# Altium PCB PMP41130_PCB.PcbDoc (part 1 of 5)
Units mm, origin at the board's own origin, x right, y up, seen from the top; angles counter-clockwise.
Board outline 74.13 x 200.91 mm, 6 copper layers (Top Layer, Layer 1, Inside Layer 1, Inside Layer 2, Layer 2, Bottom Layer), stack 2.208 mm thick; 356 components, 162 nets, 889 pads, 1511 vias.
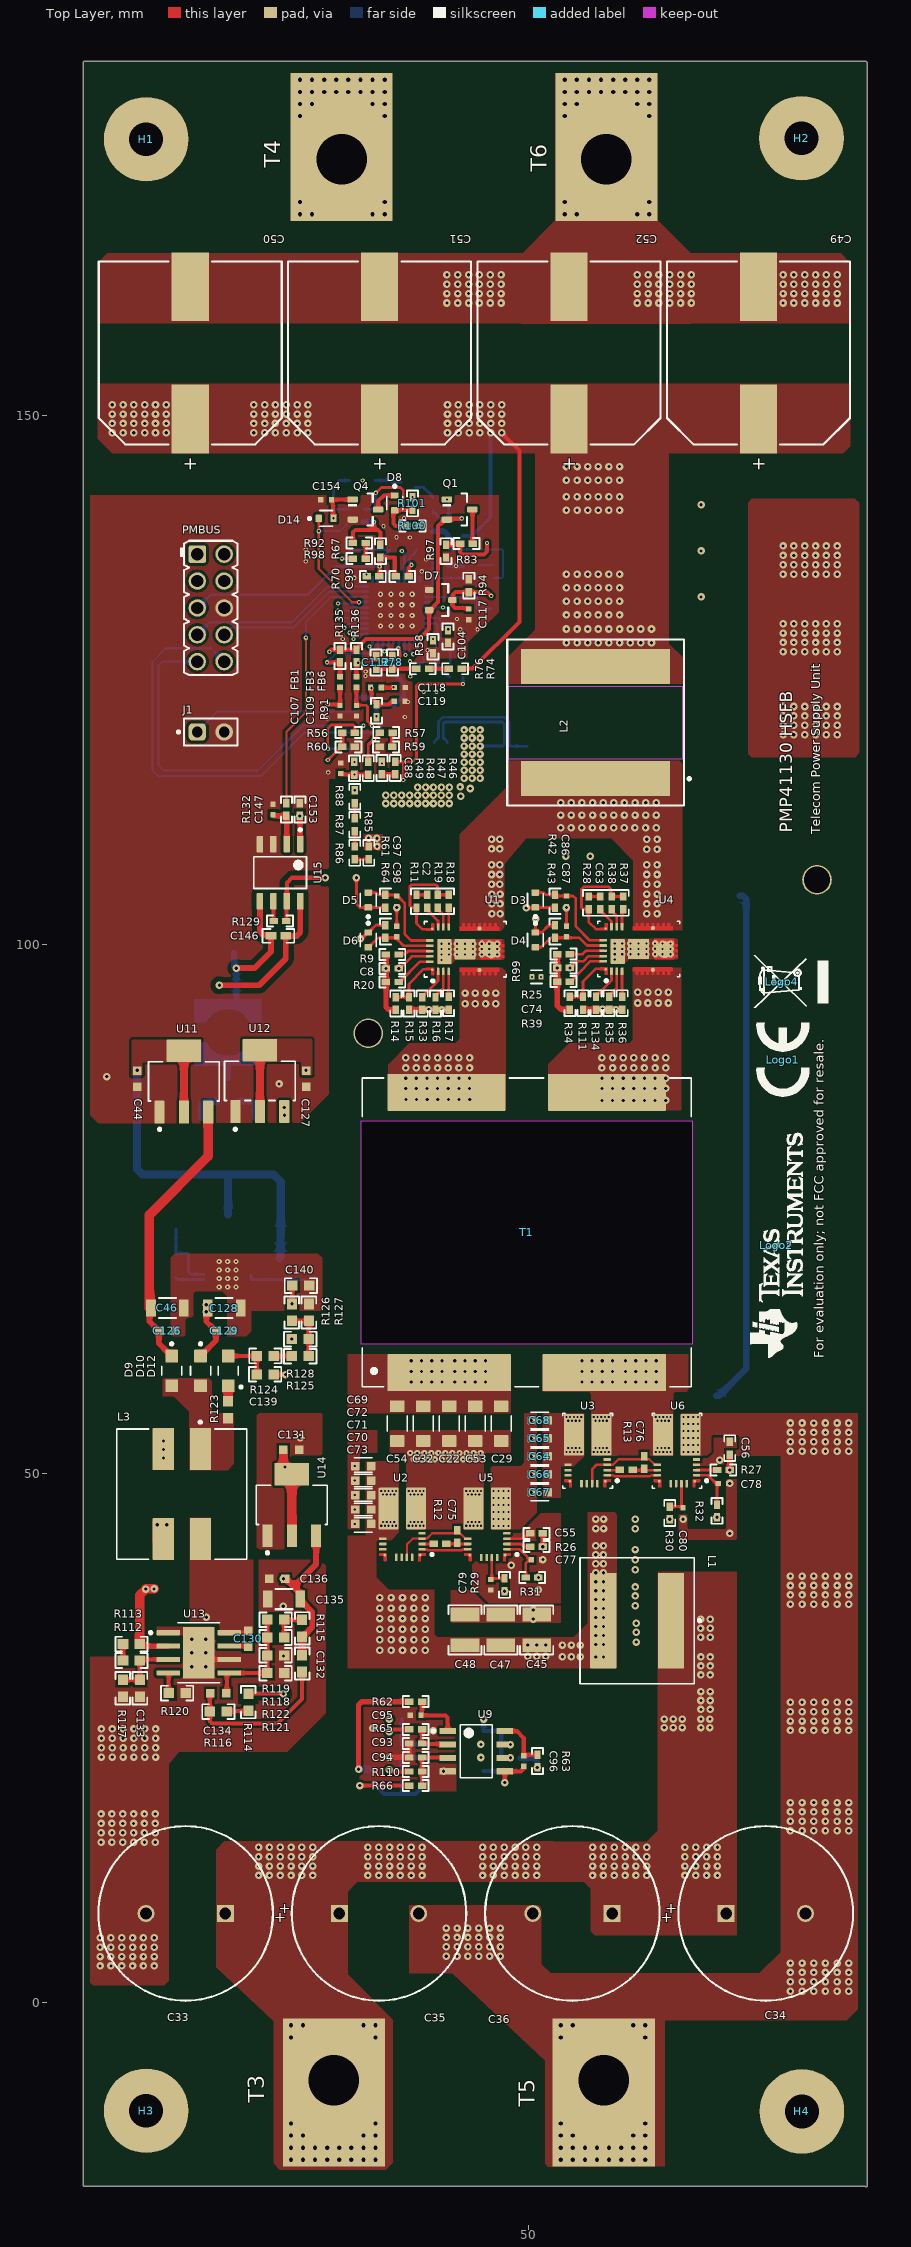
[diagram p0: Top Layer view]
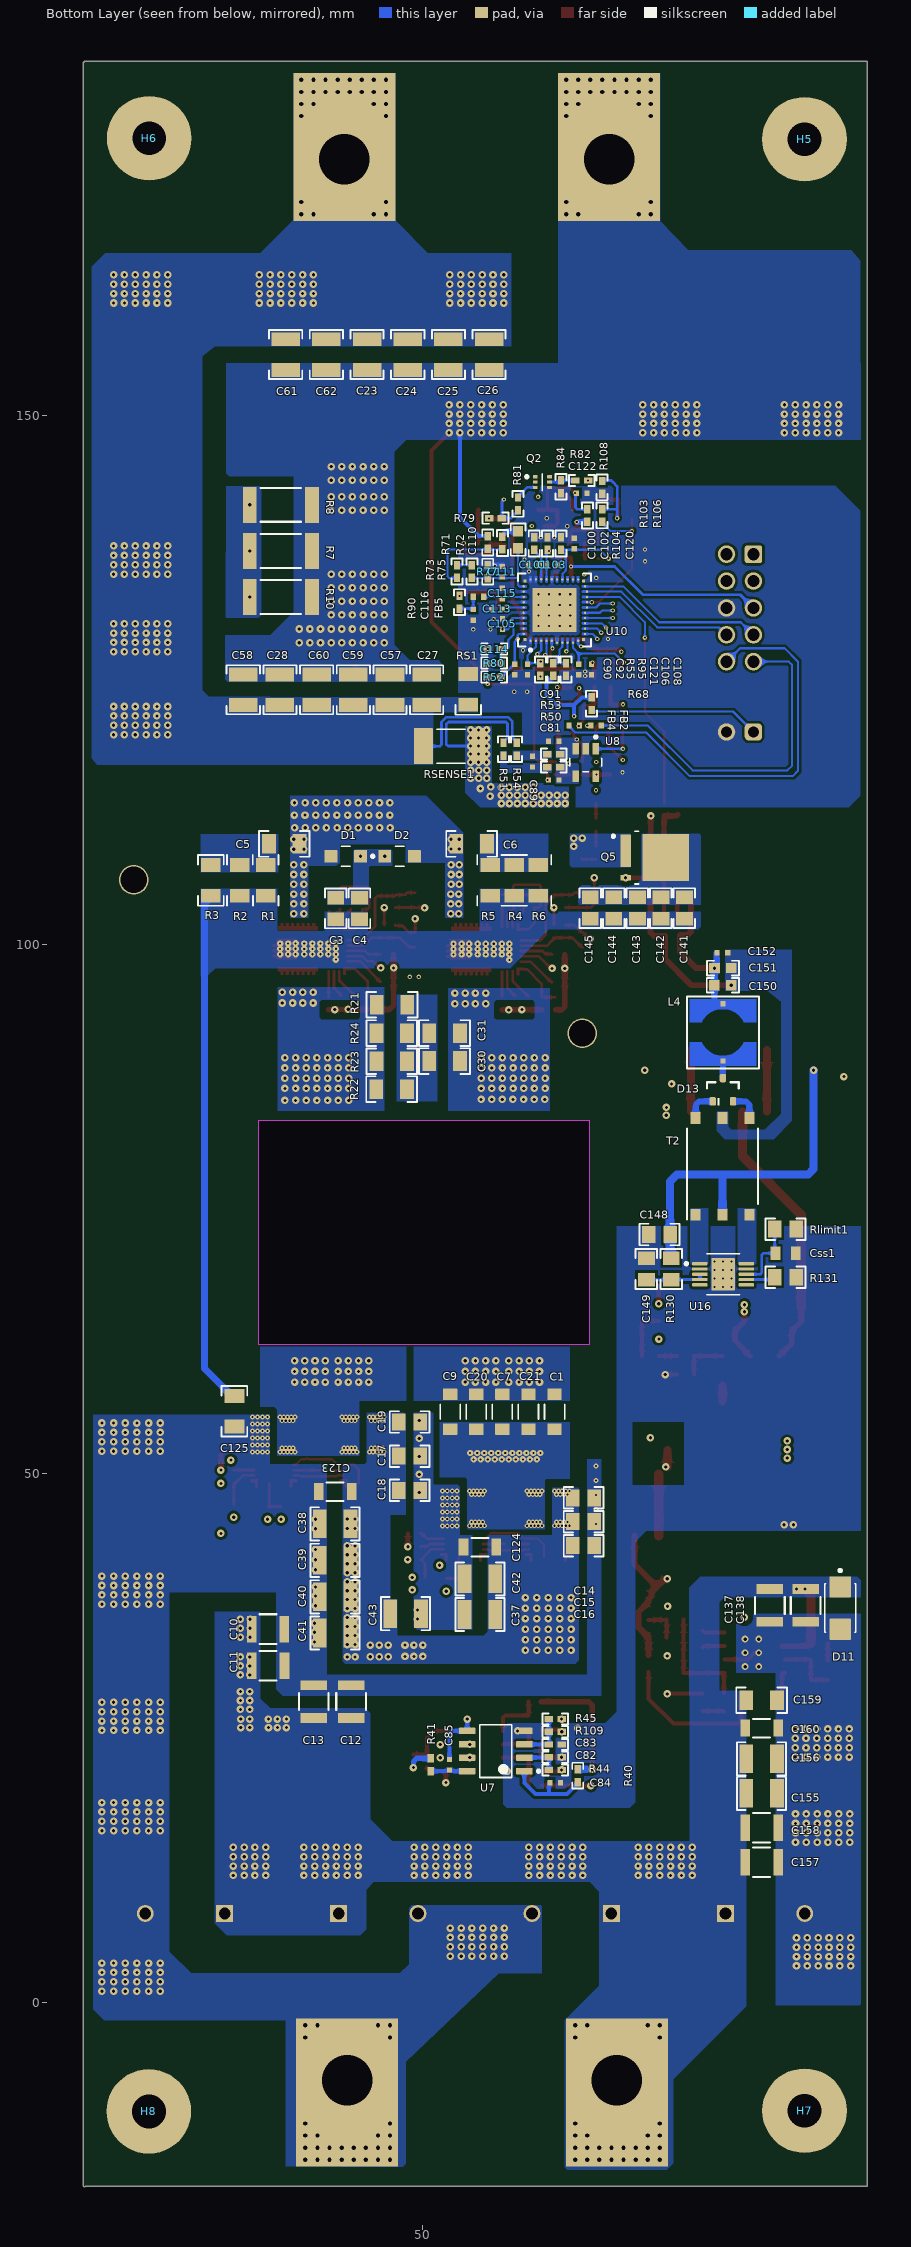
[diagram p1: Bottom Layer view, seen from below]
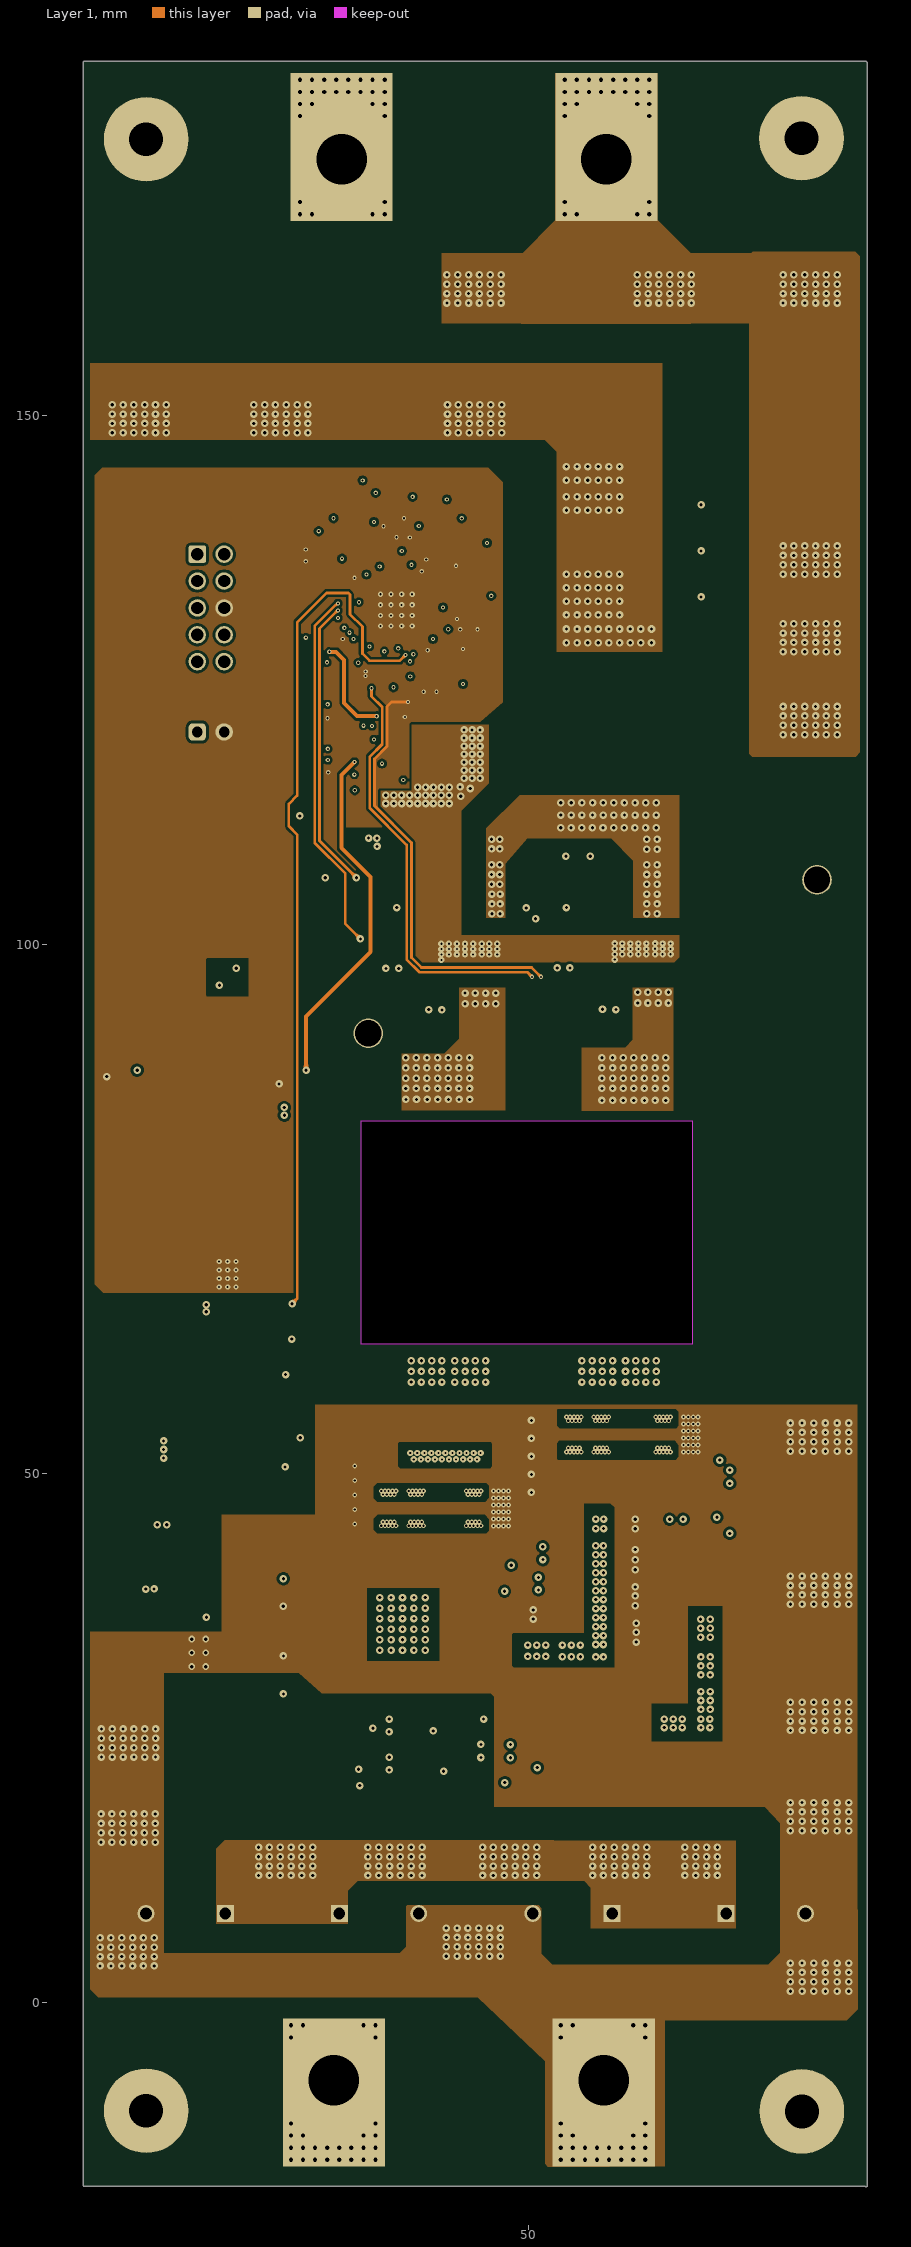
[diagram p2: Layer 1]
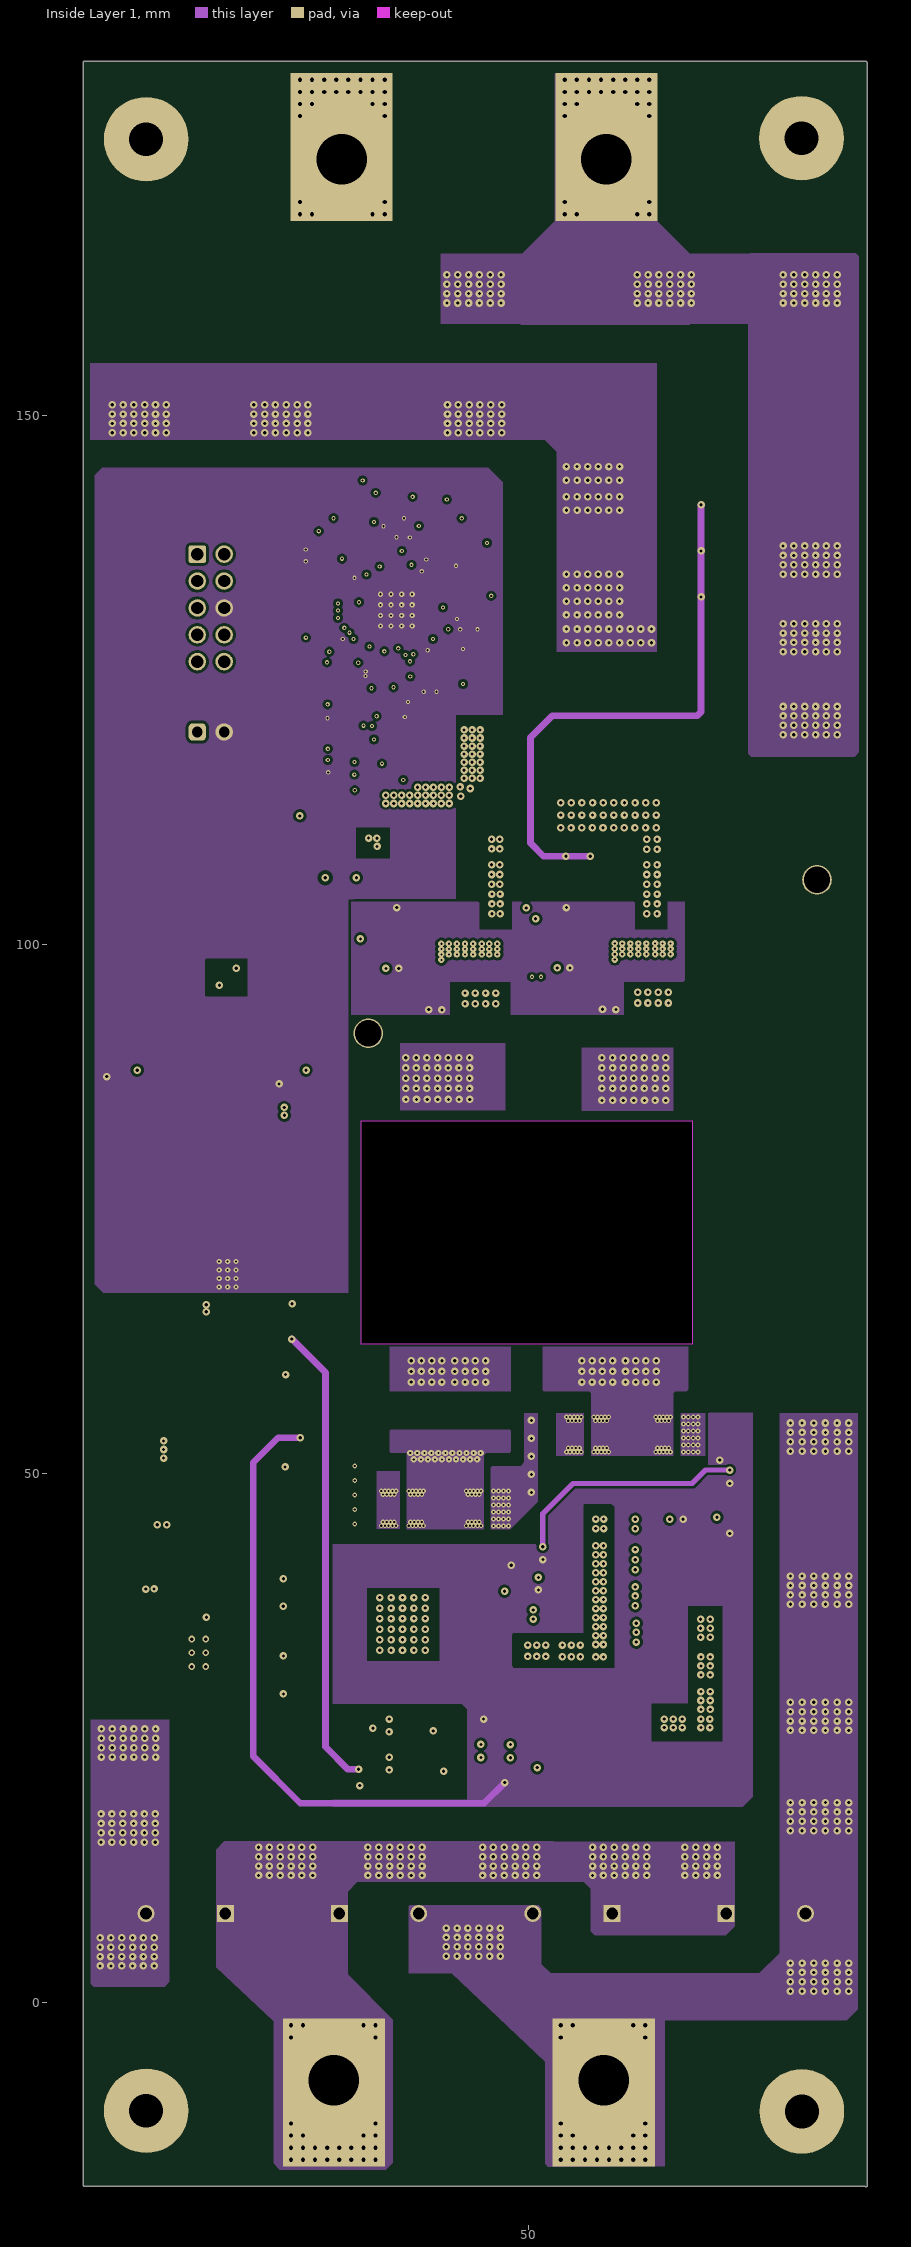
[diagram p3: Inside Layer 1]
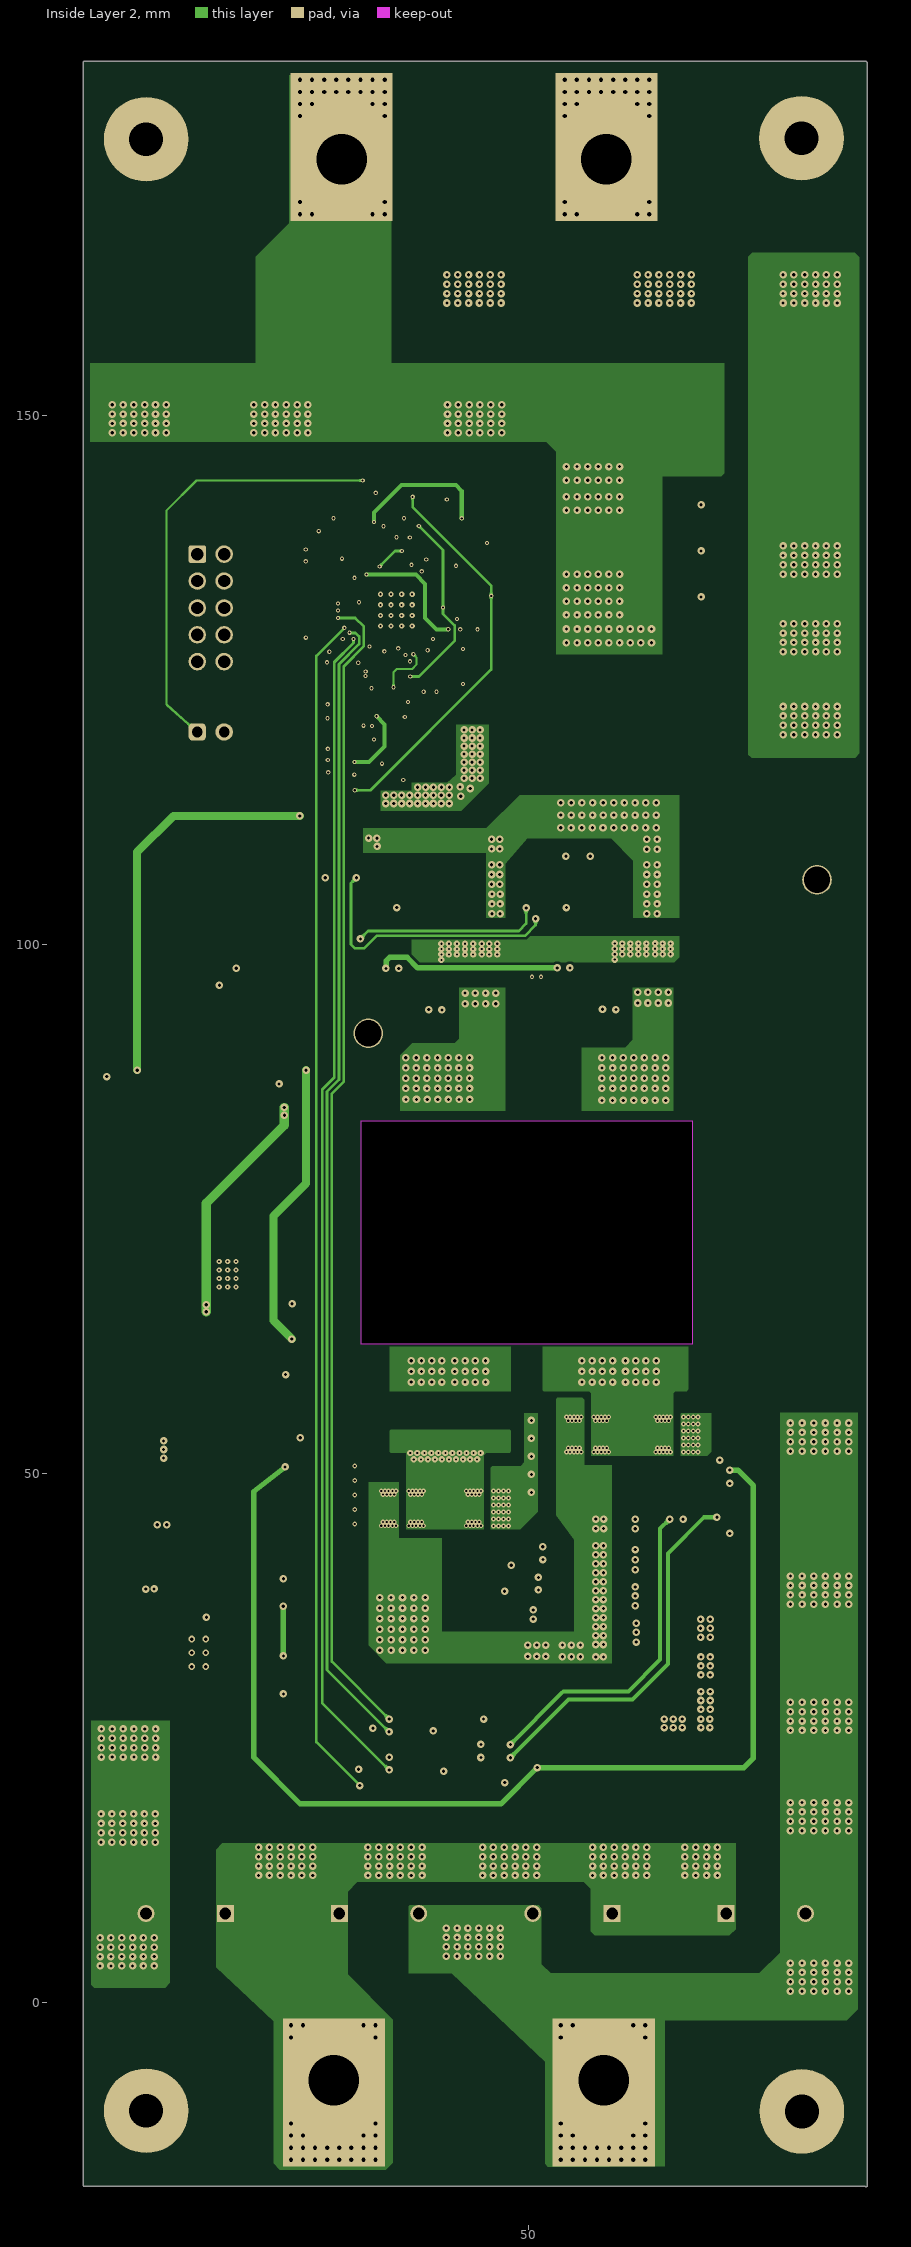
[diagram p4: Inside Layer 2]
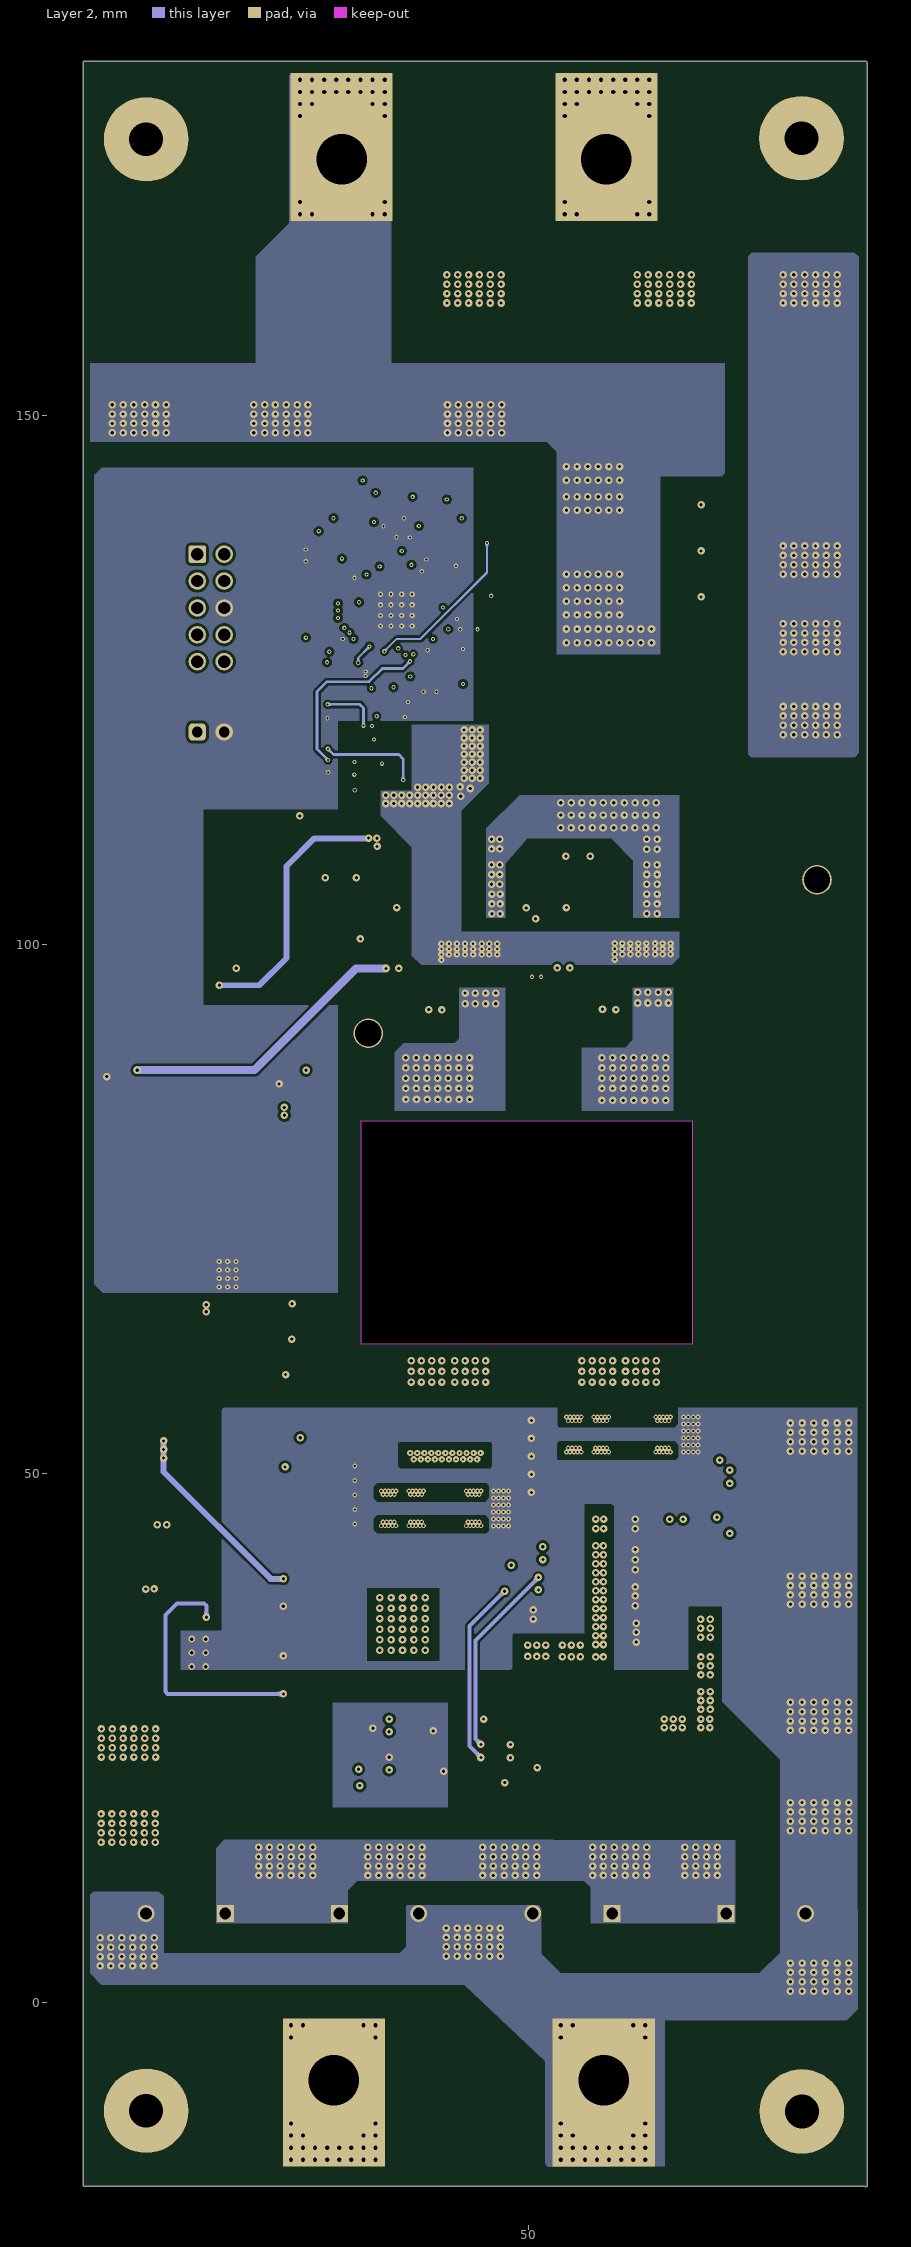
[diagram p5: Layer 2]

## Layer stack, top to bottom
Top Solder: solder mask 0.0102, Solder Resist, Dk 3.5
Top Layer: signal copper 0.07
Dielectric 3: prepreg 0.0711, PP-006, Dk 4.1
Layer 1: signal copper 0.07
Dielectric 1: prepreg 0.0711, PP-006, Dk 4.1
Inside Layer 1: signal copper 0.07
Dielectric1: core 1.5037, FR-4 High Tg, Dk 4.8
Inside Layer 2: signal copper 0.07
Dielectric 2: prepreg 0.0711, PP-006, Dk 4.1
Layer 2: signal copper 0.07
Dielectric 4: prepreg 0.0711, PP-006, Dk 4.1
Bottom Layer: signal copper 0.07
Bottom Solder: solder mask 0.0102, Solder Resist, Dk 3.5

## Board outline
7.918,-17.3 7.918,183.3 7.919,183.313 cw(c8.046,183.325) 8.046,183.453 81.855,183.453 cw(c81.855,183.325) 81.967,183.386 cw(c81.919,183.268) 82.046,183.268 82.046,-17.331 cw(c81.919,-17.331) 81.839,-17.43 8.077,-17.43 8.048,-17.427 cw(c8.046,-17.3)

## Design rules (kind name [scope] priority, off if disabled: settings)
AcuteAngle [All] p1: minimum=4.50000000000000E+0001 checktracksonly=FALSE
AssemblyTestPointUsage [All] p1: valid=2
BoardOutlineClearance BoardOutlineClearance_MountingHoles [OnCopper and InComponentClass('Mounting Holes')] p1: gap=1 ignorepadtopadclearanceinfootprint=FALSE
BoardOutlineClearance BoardOutlineClearance_Poly [OnCopper and IsPoly] p2: gap=0.635 ignorepadtopadclearanceinfootprint=FALSE
BoardOutlineClearance [OnCopper and Not InComponentClass('Logo') and not InComponentClass('FiducialMark') and not InRegion(1000,500,4000,800) and not InPoly] p3: gap=1.016 ignorepadtopadclearanceinfootprint=FALSE
Clearance Clearance_Keepouts [((IsTrack Or IsArc) And Not InPoly) And IsFree and IsKeepOut vs ((IsTrack Or IsArc) And Not InPoly) And IsFree and IsKeepOut] p1: gap=3 ignorepadtopadclearanceinfootprint=TRUE
Clearance Clearance_FiducialMark [IsKeepOut and InComponentClass('FiducialMark') vs IsPad and InComponentClass('FiducialMark')] p2: gap=3 ignorepadtopadclearanceinfootprint=FALSE
Clearance RPI_GaN [InComponent('U2') or InComponent('U3') or  InComponent('U5') or InComponent('U6') vs InNet('HB1_MID') or InNet('HB2_MID') or InNet('HS_Drain') or InNet('SW1') or InNet('SW2')] p3: gap=0.23 ignorepadtopadclearanceinfootprint=TRUE
Clearance PRI_GaN1 [InNet('SW1','SW2') vs InNet('HB1_MID','HB2_MID')] p4: gap=0.23 ignorepadtopadclearanceinfootprint=TRUE
Clearance MV_TOP [InNetClass('MIDVOLTAGE') vs OnLayer('Top Layer')] p5: gap=0.5 ignorepadtopadclearanceinfootprint=TRUE
Clearance MV_BOTTOM [InNetClass('MIDVOLTAGE') vs OnLayer('Bottom Layer')] p6: gap=0.5 ignorepadtopadclearanceinfootprint=TRUE
Clearance MV_MID [(OnMultiLayer Or OnMid) And InNetClass('MIDVOLTAGE') vs OnMid And Not InNetClass('MIDVOLTAGE')] p7: gap=0.35 ignorepadtopadclearanceinfootprint=TRUE
Clearance Clearance_Poly [InPolygon] p8: gap=0.254 ignorepadtopadclearanceinfootprint=TRUE
Clearance [All] p9: gap=0.2 ignorepadtopadclearanceinfootprint=TRUE
ComponentClearance ComponentClearance_MountingHoles_FiducialMarks [InComponentClass('Mounting Holes') vs InComponentClass('FiducialMark')] p1: gap=1.27 collisioncheckmode=3 verticalgap=0.254 showdistances=FALSE
ComponentClearance ComponentClearance_Shunt [InComponentClass('Header') vs InComponentClass('Shunt')] p2: gap=0 collisioncheckmode=3 verticalgap=0 showdistances=FALSE
ComponentClearance ComponentClearance_Logo [InComponentClass('Logo')] p3: gap=0.762 collisioncheckmode=3 verticalgap=0.254 showdistances=FALSE
ComponentClearance ComponentClearance_ScrewToNut [(HasFootprint('NY PMS 440 0025 PH')) vs (HasFootprint('Keystone_1902C'))] p4: gap=0.127 collisioncheckmode=3 verticalgap=0.254 showdistances=FALSE
ComponentClearance ComponentClearance_MountingHoles [InComponentClass('Mounting Holes')] p5: gap=2.54 collisioncheckmode=3 verticalgap=2540 showdistances=FALSE
ComponentClearance ComponentClearance_SmallPassives [HasFootprint('0201*') or HasFootprint('0402*') or HasFootprint('0508') or HasFootprint('0603*') or HasFootprint('0612') or HasFootprint('0805*') or HasFootprint('0815*') or HasFootprint('0830*') or HasFootprint('1206*') or HasFootprint('1210*') or HasFootprint('1808*') or HasFootprint('1812*') or HasFootprint('1825*') or HasFootprint('2010*') or HasFootprint('2220*') or HasFootprint('2225*') or HasFootprint('2512*') or HasFootprint('2728*') or HasFootprint('3518*') vs HasFootprint('0201*') or HasFootprint('0402*') or HasFootprint('0508') or HasFootprint('0603*') or HasFootprint('0612') or HasFootprint('0805*') or HasFootprint('0815*') or HasFootprint('0830*') or HasFootprint('1206*') or HasFootprint('1210*') or HasFootprint('1808*') or HasFootprint('1812*') or HasFootprint('1825*') or HasFootprint('2010*') or HasFootprint('2220*') or HasFootprint('2225*') or HasFootprint('2512*') or HasFootprint('2728*') or HasFootprint('3518*')] p6: gap=0.38 collisioncheckmode=3 verticalgap=0.254 showdistances=FALSE
ComponentClearance ComponentClearance_THtoSMT [IsThruComponent vs IsSMTComponent] p7: gap=0.762 collisioncheckmode=3 verticalgap=0.762 showdistances=FALSE
ComponentClearance ComponentClearance_THtoTH [IsThruComponent vs IsThruComponent] p8: gap=0.508 collisioncheckmode=3 verticalgap=0.762 showdistances=FALSE
ComponentClearance [All] p9: gap=0.508 collisioncheckmode=3 verticalgap=0.254 showdistances=FALSE
DiffPairsRouting [All] p1: maxlimit=2.54 minlimit=0.254 mostfreqgap=0.254 toplayer_minwidth=0.381 toplayer_maxwidth=0.381 toplayer_prefwidth=0.381 midlayer1_minwidth=0.381 midlayer1_maxwidth=0.381 midlayer1_prefwidth=0.381 midlayer2_minwidth=0.381 midlayer2_maxwidth=0.381 midlayer2_prefwidth=0.381 midlayer3_minwidth=0.381 midlayer3_maxwidth=0.381 midlayer3_prefwidth=0.381 midlayer4_minwidth=0.381 midlayer4_maxwidth=0.381 midlayer4_prefwidth=0.381 bottomlayer_minwidth=0.381 bottomlayer_maxwidth=0.381 bottomlayer_prefwidth=0.381 maxuncoupledlength=25.4
FabricationTestPointUsage TestPointUsage [All] p1: valid=2 allowmultiple=FALSE
FabricationTestpoint Testpoint [All] p1: side=3 testpointundercomponent=TRUE minsize=1.016 maxsize=2.54 preferedsize=1.524 minholesize=0 maxholesize=1.016 preferedholesize=0.813 testpointgrid=0.025 allowsidetop=TRUE allowsidebottom=TRUE usegrid=TRUE gridtolerance=0
FanoutControl Fanout_LCC [IsLCC] p1: bgadir=Out bgaviamode=Centered fanoutstyle=Auto fanoutdirection=Alternating viagrid=0.025 // Fanout_LCC (Default Rule)
FanoutControl Fanout_BGA [IsBGA] p2: bgadir=Out bgaviamode=Centered fanoutstyle=Auto fanoutdirection=Alternating viagrid=0.025 // Fanout_BGA (Default Rule)
FanoutControl Fanout_Default [All] p4: bgadir=Out bgaviamode=Centered fanoutstyle=Auto fanoutdirection=Alternating viagrid=0.025 // Fanout_Default (Default Rule)
FanoutControl Fanout_Small [(CompPinCount < 5)] p5: bgadir=Out bgaviamode=Centered fanoutstyle=Auto fanoutdirection=OutThenIn viagrid=0.025 // Fanout_Small (Default Rule)
Height [All] p1: minheight=0 maxheight=150 prefheight=12.7
HoleSize [All] p1: absolutevalues=TRUE maxlimit=6.375 minlimit=0.2 maxpercent=80.000 minpercent=20.000
MinimumAnnularRing MinimumAnnularRing_ThermalPadVias [IsVia and InAnyComponent] p1: minimumring=0.15
MinimumAnnularRing [All] p2: minimumring=0.2
MinimumSolderMaskSliver MinimumSolderMaskSliver_Logo [InComponentClass('Logo') vs InComponentClass('Logo')] p1: minsoldermaskwidth=0.018
MinimumSolderMaskSliver [All] p2: minsoldermaskwidth=0.1
PlaneConnect [All] p1: planeconnectstyle=Relief reliefexpansion=0.254 reliefentries=4 reliefconductorwidth=0.254 reliefairgap=0.254
PolygonConnect [All] p1: connectstyle=Direct reliefconductorwidth=0.254 reliefentries=4 polygonreliefangle="90 Angle" airgapwidth=0.254
RoutingVias ThermalPadVias [IsVia and InAnyComponent] p1: holewidth=0.2 width=0.5 viastyle="Through Hole" minholewidth=0.2 minwidth=0.5 maxholewidth=0.33 maxwidth=0.6
RoutingVias [All] p2: holewidth=0.406 width=0.864 viastyle="Through Hole" minholewidth=0.2 minwidth=0.61 maxholewidth=1.016 maxwidth=1.651
SilkToBoardRegionClearance [Not ((IsComment or IsDesignator) And (Hide <> 'False')) and not InRegion(1000,500,4000,800)] p1:
SilkToSilkClearance SilkToSilkClearance_Pb-FreeLogo [(HasFootprint('Pb-Free_Overlay_Medium') OR HasFootprint('Pb-Free_Overlay_Small')) vs (HasFootprint('Pb-Free_Overlay_Medium') OR HasFootprint('Pb-Free_Overlay_Small'))] p1: silktosilkclearance=0
SilkToSilkClearance [All] p2: silktosilkclearance=0.1
SilkToSolderMaskClearance SilkToComponentPadClearance [(IsPad or IsFill or IsRegion) and InAnycomponent] p1: minsilkscreentomaskgap=0.127 clearancetoexposedcopper=TRUE
SilkToSolderMaskClearance "Silk to Solder Mask Opening" [All] p2: minsilkscreentomaskgap=0.1 clearancetoexposedcopper=FALSE
SolderMaskExpansion [All] p1: expansion=0.05 istentingtop=FALSE
UnRoutedNet [All] p1: checkbadconnections=TRUE
Width [All] p1: maxlimit=2.54 minlimit=0.152 preferedwidth=0.254 checkconnectedcopper=TRUE
13 further rules are at their usual default settings.

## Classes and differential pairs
net class MIDVOLTAGE: 15V0_ACL HS_Drain NetC141_2 NetQ5_4 NetR129_1 SR_Drain SW1 SW2 SW3 SW4 SW_AUX VIN_POS VOUT
component class Header: J1 PMBUS
component class PMP41130_AUX: C44 C46 C126 C127 C128 C129 C130 C131 C132 C133 C134 C135 C136 C137 C138 C139 C140 C148 C149 C150 C151 C152 C155 C156 C157 C158 C159 C160 Css1 D9 D10 D11 D12 D13 L3 L4 R112 R113 R114 R115 R116 R117 R118 R119 R120 R121 R122 R123 R124 R125 R126 R127 R128 R130 R131 Rlimit1 T2 U11 U12 U13 U14 U16
component class PMP41130_CTRL: C99 C100 C101 C102 C103 C104 C105 C106 C107 C108 C109 C110 C111 C112 C113 C114 C115 C116 C117 C118 C119 C120 C121 C122 C154 D7 D8 D14 FB1 FB2 FB3 FB4 FB5 FB6 J1 PMBUS Q1 Q2 Q4 R67 R68 R70 R71 R72 R73 R74 R75 R76 R77 R78 R79 R80 R81 R82 R83 R84 R85 R86 R87 R88 R90 R91 R92 R94 R95 R97 R98 R99 R100 R101 R103 R104 R106 R108 R135 R136 U10
component class PMP41130_PWR: C1 C2 C3 C4 C5 C6 C7 C8 C9 C10 C11 C12 C13 C14 C15 C16 C17 C18 C19 C20 C21 C22 C23 C24 C25 C26 C27 C28 C29 C30 C31 C32 C33 C34 C35 C36 C37 C38 C39 C40 C41 C42 C43 C45 C47 C48 C49 C50 C51 C52 C53 C54 C55 C56 C57 C58 C59 C60 C61 C62 C63 C64 C65 C66 C67 C68 C69 C70 C71 C72 C73 C74 C75 C76 C77 C78 C79 C80 C81 C82 C83 C84 C85 C86 C87 C88 C89 C90 C91 C92 C93 C94 C95 C96 C97 C98 C123 C124 C125 C141 C142 C143 C144 C145 C146 C147 C153 D1 D2 D3 D4 D5 D6 L1 L2 Q5 R1 R2 R3 R4 R5 R6 R7 R8 R9 R10 R11 R12 R13 R14 R15 R16 R17 R18 R19 R20 R21 R22 R23 R24 R25 R26 R27 R28 R29 R30 R31 R32 R33 R34 R35 R36 R37 R38 R39 R40 R41 R42 R43 R44 R45 R46 R47 R48 R49 R50 R51 R52 R53 R54 R55 R56 R57 R58 R59 R60 R61 R62 R63 R64 R65 R66 R109 R110 R111 R129 R132 R134 RS1 RSENSE1 T1 U1 U2 U3 U4 U5 U6 U7 U8 U9 U15
component class "Mounting Holes": H1 H2 H3 H4
component class Logo: Logo2
component class PMP41130_Hardware: H1 H2 H3 H4 H5 H6 H7 H8 Logo1 Logo2 Logo3 Logo4 T3 T4 T5 T6

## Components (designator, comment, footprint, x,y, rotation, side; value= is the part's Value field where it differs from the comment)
C1 "C3216X6S2A106K160AC" FP-C3216X6S2A106K160AC_1206-MFG 37.495,55.799 r90 bottom value=10µF
C2 "GRM155R61E474KE01D" 0402 40.424,104.055 r270 top value=0.47uF
C3 "C2012X7T2E104M125AE" 0805_HV 58.177,103.384 r270 bottom value=0.1uF
C4 "C2012X7T2E104M125AE" 0805_HV 55.935,103.384 r270 bottom value=0.1uF
C5 "VJ1206Y471KXEAT5Z" 1206 63.046,109.473 r180 bottom value=470pF
C6 "VJ1206Y471KXEAT5Z" 1206 45.335,109.473 r0 bottom value=470pF
C7 "C3216X6S2A106K160AC" FP-C3216X6S2A106K160AC_1206-MFG 42.43,55.799 r90 bottom value=10µF
C8 "GRM155R61E105MA12D" 0402 37.133,97.697 r180 top value=1uF
C9 "C3216X6S2A106K160AC" FP-C3216X6S2A106K160AC_1206-MFG 47.366,55.799 r90 bottom value=10µF
C10 "885012209071" WCAP-CSGP_1210_L3.2W2.5H2.5 64.581,35.256 r180 bottom
C11 "885012209071" WCAP-CSGP_1210_L3.2W2.5H2.5 64.573,31.794 r180 bottom
C12 "885012209071" WCAP-CSGP_1210_L3.2W2.5H2.5 56.73,28.398 r90 bottom
C13 "885012209071" WCAP-CSGP_1210_L3.2W2.5H2.5 60.263,28.398 r90 bottom
C14 "C2012X7S2A105K125AB" 0805_HV 34.746,47.658 r0 bottom value=1uF
C15 "C2012X7S2A105K125AB" 0805_HV 34.746,45.403 r0 bottom value=1uF
C16 "C2012X7S2A105K125AB" 0805_HV 34.746,43.148 r0 bottom value=1uF
C17 "C2012X7S2A105K125AB" 0805_HV 51.199,48.369 r0 bottom value=1uF
C18 "C2012X7S2A105K125AB" 0805_HV 51.199,51.597 r0 bottom value=1uF
C19 "C2012X7S2A105K125AB" 0805_HV 51.199,54.825 r0 bottom value=1uF
C20 "C3216X6S2A106K160AC" FP-C3216X6S2A106K160AC_1206-MFG 44.898,55.799 r90 bottom value=10µF
C21 "C3216X6S2A106K160AC" FP-C3216X6S2A106K160AC_1206-MFG 39.963,55.799 r90 bottom value=10µF
C22 "C3216X6S2A106K160AC" FP-C3216X6S2A106K160AC_1206-MFG 42.504,54.684 r90 top value=10µF
C23 "C3225X7S2A475K200AE" 1210 55.219,155.723 r270 bottom value=4.7uF
C24 "C3225X7S2A475K200AE" 1210 51.374,155.723 r270 bottom value=4.7uF
C25 "C3225X7S2A475K200AE" 1210 47.529,155.723 r270 bottom value=4.7uF
C26 "C3225X7S2A475K200AE" 1210 43.684,155.723 r270 bottom value=4.7uF
C27 "C3225X7S2A475K200AE" 1210 49.581,124.046 r90 bottom value=4.7uF
C28 "C3225X7S2A475K200AE" 1210 63.454,124.046 r90 bottom value=4.7uF
C29 "C3216X6S2A106K160AC" FP-C3216X6S2A106K160AC_1206-MFG 47.416,54.684 r90 top value=10µF
C30 "VJ1206A101JXGAT5Z" 1206 47.894,88.95 r180 bottom value=100pF
C31 "VJ1206A101JXGAT5Z" 1206 47.894,91.595 r180 bottom value=100pF
C32 "C3216X6S2A106K160AC" FP-C3216X6S2A106K160AC_1206-MFG 40.049,54.684 r90 top value=10µF
C33 "ECA-2AM471" M_1600x2500 17.595,8.375 r180 top value=470uF
C34 "ECA-2AM471" M_1600x2500 72.435,8.375 r0 top value=470uF
C35 "ECA-2AM471" M_1600x2500 35.875,8.375 r0 top value=470uF
C36 "ECA-2AM471" M_1600x2500 54.155,8.375 r180 top value=470uF
C37 "C3225X7S2A475K200AE" 1210 44.553,36.635 r180 bottom value=4.7uF
C38 "C3225X7S2A475K200AE" 1210 58.236,45.202 r180 bottom value=4.7uF
C39 "C3225X7S2A475K200AE" 1210 58.236,41.751 r0 bottom value=4.7uF
C40 "C3225X7S2A475K200AE" 1210 58.236,38.299 r0 bottom value=4.7uF
C41 "C3225X7S2A475K200AE" 1210 58.246,34.885 r0 bottom value=4.7uF
C42 "C3225X7S2A475K200AE" 1210 44.553,39.993 r0 bottom value=4.7uF
C43 "C3225X7S2A475K200AE" 1210 51.577,36.71 r180 bottom value=4.7uF
C44 "885012206027" WCAP-CSGP_0603_L1.6W0.8H0.8_Reflow 13.012,87.288 r270 top
C45 "C3225X7S2A475K200AE" 1210 50.777,35.181 r90 top value=4.7uF
C46 "885012208019" WCAP-CSGP_1206_L3.2W1.6H1.6 15.871,65.607 r0 top
C47 "C3225X7S2A475K200AE" 1210 47.391,35.181 r90 top value=4.7uF
C48 "C3225X7S2A475K200AE" 1210 44.004,35.185 r90 top value=4.7uF
C49 "865080863009" WCAP-ASLI_D16H17 71.743,155.888 r270 top
C50 "865080863009" WCAP-ASLI_D16H17 18.031,155.888 r270 top
C51 "865080863009" WCAP-ASLI_D16H17 35.935,155.888 r270 top
C52 "865080863009" WCAP-ASLI_D16H17 53.839,155.888 r270 top
C53 "C3216X6S2A106K160AC" FP-C3216X6S2A106K160AC_1206-MFG 44.96,54.684 r90 top value=10µF
C54 "C3216X6S2A106K160AC" FP-C3216X6S2A106K160AC_1206-MFG 37.593,54.684 r90 top value=10µF
C55 "GRM155R61E225ME15D" 0402 50.763,44.3 r0 top value=2.2uF
C56 "GRM155R61E225ME15D" 0402 69.028,52.354 r270 top value=2.2uF
C57 "C3225X7S2A475K200AE" 1210 53.049,124.046 r90 bottom value=4.7uF
C58 "C3225X7S2A475K200AE" 1210 66.922,124.046 r90 bottom value=4.7uF
C59 "C3225X7S2A475K200AE" 1210 56.518,124.046 r90 bottom value=4.7uF
C60 "C3225X7S2A475K200AE" 1210 59.986,124.046 r90 bottom value=4.7uF
C61 "VJ1210Y104KBBAT4X" 1210 62.91,155.723 r270 bottom value=0.1uF
C62 "VJ1210Y104KBBAT4X" 1210 59.064,155.723 r270 bottom value=0.1uF
C63 "GRM155R61E474KE01D" 0402 56.775,103.903 r270 top value=0.47uF
C64 "885012206120" FP-885012206120_0603-MFG 51.084,51.571 r0 top value=100nF
C65 "885012206120" FP-885012206120_0603-MFG 51.084,53.272 r0 top value=100nF
C66 "885012206120" FP-885012206120_0603-MFG 51.084,49.87 r0 top value=100nF
C67 "885012206120" FP-885012206120_0603-MFG 51.084,48.169 r0 top value=100nF
C68 "885012206120" FP-885012206120_0603-MFG 51.084,54.973 r0 top value=100nF
C69 "885012206120" FP-885012206120_0603-MFG 34.376,50.659 r0 top value=100nF
C70 "885012206120" FP-885012206120_0603-MFG 34.376,46.556 r0 top value=100nF
C71 "885012206120" FP-885012206120_0603-MFG 34.376,47.924 r0 top value=100nF
C72 "885012206120" FP-885012206120_0603-MFG 34.376,49.291 r0 top value=100nF
C73 "885012206120" FP-885012206120_0603-MFG 34.376,45.189 r0 top value=100nF
C74 "GRM155R61E105MA12D" 0402 53.316,97.752 r180 top value=1uF
C75 "GRM155R61E474KE01D" 0402 43.281,44.012 r90 top value=0.47uF
C76 "GRM155R61E474KE01D" 0402 60.93,51.008 r90 top value=0.47uF
C77 "885012205055" WCAP-CSGP_0402_L1W0.5H0.5 50.763,41.798 r0 top
C78 "885012205055" WCAP-CSGP_0402_L1W0.5H0.5 68.428,49.02 r0 top
C79 "885012005058" WCAP-CSGP_0402_L1W0.5H0.5 46.448,39.439 r270 top
C80 "885012005058" WCAP-CSGP_0402_L1W0.5H0.5 64.617,46.235 r270 top
C81 "885012005058" WCAP-CSGP_0402_L1W0.5H0.5 37.569,115.506 r180 bottom
C82 "885012005043" 0402 37.432,23.139 r180 bottom value=33pF
C83 "885012005043" 0402 37.432,24.343 r180 bottom value=33pF
C84 "885012205037" WCAP-CSGP_0402_L1W0.5H0.5 37.432,20.731 r180 bottom
C85 "885012205037" WCAP-CSGP_0402_L1W0.5H0.5 47.429,22.428 r90 bottom
C86 "885012005058" WCAP-CSGP_0402_L1W0.5H0.5 53.594,104.056 r270 top
C87 "885012005058" WCAP-CSGP_0402_L1W0.5H0.5 53.594,101.2 r90 top
C88 "885012205018" WCAP-CSGP_0402_L1W0.5H0.5 32.256,116.623 r270 top
C89 "885012005067" WCAP-CSGP_0402_L1W0.5H0.5 39.575,117.248 r270 bottom
C90 "885012205050" WCAP-CSGP_0402_L1W0.5H0.5 41.253,125.958 r270 bottom
C91 "885012005058" WCAP-CSGP_0402_L1W0.5H0.5 37.569,119.183 r0 bottom
C92 "885392005114" WCAP-CSRF_0402_L1W0.5H0.5 40.045,125.958 r270 bottom
C93 "885012005043" 0402 39.34,24.444 r180 top value=33pF
C94 "885012005043" 0402 39.34,23.115 r180 top value=33pF
C95 "885012205037" WCAP-CSGP_0402_L1W0.5H0.5 39.34,27.102 r180 top
C96 "885012205037" WCAP-CSGP_0402_L1W0.5H0.5 49.554,22.784 r270 top
C97 "885012005058" WCAP-CSGP_0402_L1W0.5H0.5 37.557,104.055 r270 top
C98 "885012005058" WCAP-CSGP_0402_L1W0.5H0.5 37.557,101.2 r90 top
C99 "GRM155R61E225ME15D" 0402 38.072,134.757 r0 top value=2.2uF
C100 "GRM155R61E105MA12D" 0402 39.412,137.874 r90 bottom value=1uF
C101 "885012205050" WCAP-CSGP_0402_L1W0.5H0.5 39.45,135.847 r0 bottom
C102 "GRM155R61E475ME15" 0402 38.157,137.874 r90 bottom value=4.7uF
C103 "885012205050" WCAP-CSGP_0402_L1W0.5H0.5 37.701,135.847 r180 bottom
C104 "GRM155R61E475ME15" 0402 42.397,129.073 r270 top value=4.7uF
C105 "885012205050" WCAP-CSGP_0402_L1W0.5H0.5 42.419,130.26 r90 bottom
C106 "885012005058" WCAP-CSGP_0402_L1W0.5H0.5 35.214,125.958 r270 bottom
C107 "885012005058" WCAP-CSGP_0402_L1W0.5H0.5 32.191,122.06 r270 top
C108 "885012005058" WCAP-CSGP_0402_L1W0.5H0.5 34.007,125.958 r270 bottom
C109 "885012005058" WCAP-CSGP_0402_L1W0.5H0.5 33.74,122.06 r270 top
C110 "C0603C103K2RACTU" 0603 40.95,138.234 r270 bottom value=0.01uF
C111 "885012005067" WCAP-CSGP_0402_L1W0.5H0.5 42.431,135.197 r90 bottom
C112 "GRM155R71H223KA12D" 0402 35.604,126.628 r90 top value=0.022uF
C113 "885392005114" WCAP-CSRF_0402_L1W0.5H0.5 42.921,131.685 r0 bottom
C114 "CGA2B3X8R1H103K050BB" 0402 43.207,127.887 r180 bottom value=0.01uF
C115 "885012005055" WCAP-CSGP_0402_L1W0.5H0.5 42.431,133.152 r90 bottom
C116 "885012005055" WCAP-CSGP_0402_L1W0.5H0.5 45.188,131.126 r270 bottom
C117 "885012005055" WCAP-CSGP_0402_L1W0.5H0.5 44.363,131.17 r270 top
C118 "885012205092" WCAP-CSGP_0402_L1W0.5H0.5 37.847,124.254 r0 top
C119 "885012005067" WCAP-CSGP_0402_L1W0.5H0.5 37.823,122.963 r0 top
C120 "885012205044" WCAP-CSGP_0402_L1W0.5H0.5 35.646,137.874 r90 bottom
C121 "GRM155R61E225ME15D" 0402 36.422,125.958 r270 bottom value=2.2uF
C122 "885012205062" WCAP-CSGP_0402_L1W0.5H0.5 34.924,142.629 r180 bottom
C123 "885012208118" WCAP-CSGP_1206_L3.2W1.6H1.25 58.234,48.248 r180 bottom
C124 "885012208118" WCAP-CSGP_1206_L3.2W1.6H1.25 44.553,42.995 r180 bottom
C125 "VJ1206Y103KXGAT5Z" 1206 67.752,55.847 r270 bottom value=0.01uF
C126 "885012206052" WCAP-CSGP_0603_L1.6W0.8H0.8_Reflow 15.871,63.453 r0 top
C127 "885012206027" WCAP-CSGP_0603_L1.6W0.8H0.8_Reflow 28.976,87.288 r270 top
C128 "885012208019" WCAP-CSGP_1206_L3.2W1.6H1.6 21.243,65.599 r0 top
C129 "885012206052" WCAP-CSGP_0603_L1.6W0.8H0.8_Reflow 21.254,63.453 r0 top
C130 "885012206085" WCAP-CSGP_0603_L1.6W0.8H0.8_Reflow 23.514,34.326 r90 top
C131 "885012206027" WCAP-CSGP_0603_L1.6W0.8H0.8_Reflow 27.587,52.2 r180 top
C132 "C0603C223K5RACTU" 0603 28.607,31.999 r270 top value=0.022uF
C133 "HMK107B7104KAHT" 0603 13.278,29.659 r270 top value=0.1uF
C134 "885012206085" WCAP-CSGP_0603_L1.6W0.8H0.8_Reflow 20.688,29.21 r0 top
C135 "885012208019" WCAP-CSGP_1206_L3.2W1.6H1.6 26.898,38.083 r180 top
C136 "885012206052" WCAP-CSGP_0603_L1.6W0.8H0.8_Reflow 26.267,39.991 r180 top
C137 "885012209071" WCAP-CSGP_1210_L3.2W2.5H2.5 17.141,37.493 r270 bottom
C138 "885012209071" WCAP-CSGP_1210_L3.2W2.5H2.5 13.77,37.493 r270 bottom
C139 "C0603C102J5GAC" 0603 25.112,59.331 r0 top value=1000pF
C140 "GRM188C71E225KE11D" 0603 28.483,67.726 r0 top value=2.2uF
C141 "C2012X7S2A105K125AB" 0805_HV 25.227,103.4 r90 bottom value=1uF
C142 "C2012X7S2A105K125AB" 0805_HV 27.451,103.4 r90 bottom value=1uF
C143 "C2012X7S2A105K125AB" 0805_HV 29.675,103.4 r90 bottom value=1uF
C144 "C2012X7S2A105K125AB" 0805_HV 31.898,103.4 r90 bottom value=1uF
C145 "C2012X7S2A105K125AB" 0805_HV 34.122,103.4 r90 bottom value=1uF
C146 "C1005JB1V105K050BC" 0402M 26.363,100.777 r180 top value=1uF
C147 "GRM155R61E105MA12D" 0402 28.392,112.721 r270 top value=1uF
C148 "GRM21BR61E106MA73L" 0805_HV 27.579,72.547 r0 bottom value=10uF
C149 "GRM21BR71E104KA01L" 0805_HV 28.819,69.286 r270 bottom value=0.1uF
C150 "GRM188R6YA475KE15D" 0603 21.585,96.11 r180 bottom value=4.7uF
C151 "GRM188R6YA475KE15D" 0603 21.579,97.732 r180 bottom value=4.7uF
C152 "885012205092" WCAP-CSGP_0402_L1W0.5H0.5 21.635,99.193 r180 bottom
C153 "885012005059" WCAP-CSGP_0402_L1W0.5H0.5 25.852,112.721 r270 top
C154 "885012205092" WCAP-CSGP_0402_L1W0.5H0.5 30.879,141.991 r180 top
C155 "C3225X7S2A475K200AE" 1210 17.925,19.726 r180 bottom value=4.7uF
C156 "C3225X7S2A475K200AE" 1210 17.925,22.985 r180 bottom value=4.7uF
C157 "885012209071" WCAP-CSGP_1210_L3.2W2.5H2.5 17.925,13.209 r180 bottom
C158 "885012209071" WCAP-CSGP_1210_L3.2W2.5H2.5 17.925,16.467 r180 bottom
C159 "C3216X7R2A105M160AA" 1206 17.925,28.519 r180 bottom value=1uF
C160 "885012208118" WCAP-CSGP_1206_L3.2W1.6H1.25 17.925,25.886 r0 bottom
Css1 "885012207021" WCAP-CSGP_0805_L2W1.25H1.25 15.661,70.782 r180 bottom
D1 "PNE20020ERX" FP-PNE20020ERX_SOD123W-MFG 57.236,108.299 r0 bottom
D2 "PNE20020ERX" FP-PNE20020ERX_SOD123W-MFG 52.139,108.299 r180 bottom
D3 "SDM20U40-7" FP-SDM20U40-7_SOD523-MFG 50.658,104.17 r90 top
D4 "SDM20U40-7" FP-SDM20U40-7_SOD523-MFG 50.658,100.396 r270 top
D5 "SDM20U40-7" FP-SDM20U40-7_SOD523-MFG 34.856,104.17 r90 top
D6 "SDM20U40-7" FP-SDM20U40-7_SOD523-MFG 34.856,100.396 r270 top
D7 "BAV99,215" SOT-23L 41.718,132.525 r0 top value=100V
D8 "SDM20U40-7" FP-SDM20U40-7_SOD523-MFG 37.366,141.704 r270 top
D9 "PNE20020ERX" FP-PNE20020ERX_SOD123W-MFG 16.271,59.667 r270 top
D10 "PNE20020ERX" FP-PNE20020ERX_SOD123W-MFG 19.006,59.667 r270 top
D11 "1SMA70AT3G" FP-1SMA70AT3G_SMA-MFG 10.494,37.239 r270 bottom
D12 "PNE20020ERX" FP-PNE20020ERX_SOD123W-MFG 21.612,59.667 r90 top
D13 "BAV70-E3-08" SOT-23L 21.583,86.239 r90 bottom value=70V
D14 "SDM20U40-7" FP-SDM20U40-7_SOD523-MFG 30.879,140.242 r0 top
FB1 "7427927141" WE-CBF_0402_L1W0.5H0.5_HS/WB 32.191,124.77 r270 top
FB2 "7427927141" WE-CBF_0402_L1W0.5H0.5_HS/WB 33.575,120.667 r180 bottom
FB3 "7427927141" WE-CBF_0402_L1W0.5H0.5_HS/WB 33.74,124.77 r270 top
FB4 "7427927141" WE-CBF_0402_L1W0.5H0.5_HS/WB 35.64,120.667 r0 bottom
FB5 "7427927141" WE-CBF_0402_L1W0.5H0.5_HS/WB 44.679,132.83 r0 bottom
FB6 "7427927141" WE-CBF_0402_L1W0.5H0.5_HS/WB 35.573,124.254 r0 top
H1 "NY PMS 440 0025 PH" "NY PMS 440 0025 PH" 13.865,176.081 r0 top locked
H2 "NY PMS 440 0025 PH" "NY PMS 440 0025 PH" 75.813,176.176 r0 top locked
H3 "NY PMS 440 0025 PH" "NY PMS 440 0025 PH" 13.865,-10.272 r0 top locked
H4 "NY PMS 440 0025 PH" "NY PMS 440 0025 PH" 75.845,-10.335 r0 top locked
H5 "1902C" Keystone_1902C 13.865,176.081 r180 bottom locked
H6 "1902C" Keystone_1902C 75.813,176.176 r180 bottom locked
H7 "1902C" Keystone_1902C 13.865,-10.272 r180 bottom locked
H8 "1902C" Keystone_1902C 75.845,-10.335 r180 bottom locked
J1 "TSW-102-07-G-S" TSW-102-07-G-S 19.969,120.052 r0 top
L1 "74439369010" FP-74439369010_SMD_11MM6_10MM5-MFG 60.276,36.051 r270 top value=1uH
L2 "74439370068" WE-XHMI_1510_L16.4W15.4H10 56.351,120.938 r180 top
L3 "MSD1260H-154KED" FP-MSD1260H-154KED_SMT_CMC_12MM3_12MM3-MFG 17.236,48.019 r270 top
L4 "744053120" WE-TPC-LH 21.583,91.655 r90 bottom value=12uH
Logo1 "CE Mark" CE_Mark_5mm 74.046,89.081 r90 top
Logo2 "Texas Instruments" TI_Stacked_Overlay_Small 73.437,71.534 r90 top
Logo3 "FCC disclaimer" FCC_disclaimer 104.847,98.264 r90 top
Logo4 "WEEE logo" WEEE_Minimum 73.948,96.42 r90 top
PMBUS "61301021121" WURTH_61301021121 19.969,131.778 r270 top
Q1 "MMBT5401LT1G" SOT-23 43.491,141.079 r0 top value="150 V"
Q2 "EMX1DXV6T5" FP-EMX1DXV6T5_SOT563-MFG 38.641,143.676 r180 bottom value=50V
Q4 "BSS138" SOT-23 34.588,141.079 r0 top value=50V
Q5 "BSC074N15NS5ATMA1" FP-BSC074N15NS5ATMA1_PG-TSON-8-3-MFG 28.033,108.18 r270 bottom
R1 "RC1206FR-0724R9L" 1206 64.794,106.032 r270 bottom value=24.9
R2 "RC1206FR-0724R9L" 1206 67.236,106.032 r270 bottom value=24.9
R3 "RC1206FR-0724R9L" 1206 69.977,106.032 r270 bottom value=24.9
R4 "RC1206FR-0724R9L" 1206 41.303,106.029 r270 bottom value=24.9
R5 "RC1206FR-0724R9L" 1206 43.591,106.032 r270 bottom value=24.9
R6 "RC1206FR-0724R9L" 1206 39.019,106.032 r270 bottom value=24.9
R7 "CRCW25124K70JNEG" 2512 63.365,137.17 r180 bottom value=4.7k
R8 "CRCW25124K70JNEG" 2512 63.365,141.525 r0 bottom value=4.7k
R9 "RC0402JR-070RL" 0402 37.133,99.022 r180 top value=0
R10 "CRCW25124K70JNEG" 2512 63.365,132.815 r180 bottom value=4.7k
R11 "RC0402JR-070RL" 0402 39.423,104.055 r270 top value=0
R12 "CRCW04023R30JNED" 0402 41.627,43.313 r0 top value=3.3
R13 "CRCW04023R30JNED" 0402 59.245,50.309 r0 top value=3.3
R14 "RC0402JR-070RL" 0402 37.462,94.38 r270 top value=0
R15 "ERJ-2RKF1002X" 0402 38.711,94.385 r270 top value=10.0k
R16 "RC0402JR-070RL" 0402 41.209,94.385 r270 top value=0
R17 "RC0402JR-070RL" 0402 42.458,94.417 r270 top value=0
R18 "RC0402JR-070RL" 0402 42.458,104.055 r90 top value=0
R19 "RC0402JR-070RL" 0402 41.414,104.055 r90 top value=0
R20 "ERJ-2RKF4701X" 0402 37.133,96.422 r180 top value=4.70k
R21 "RC1206FR-0746R4L" 1206 52.862,94.261 r0 bottom value=46.4
R22 "RC1206FR-0746R4L" 1206 52.894,86.3 r0 bottom value=46.4
R23 "RC1206FR-0746R4L" 1206 52.888,88.939 r0 bottom value=46.4
R24 "RC1206FR-0746R4L" 1206 52.888,91.595 r0 bottom value=46.4
R25 "RC0402JR-070RL" 0402 53.316,99.056 r180 top value=0
R26 "CRCW04023R30JNED" 0402 50.763,43.049 r180 top value=3.3
R27 "CRCW04023R30JNED" 0402 68.428,50.29 r180 top value=3.3
R28 "RC0402JR-070RL" 0402 55.685,103.903 r270 top value=0
R29 "RK73H1ETTP10R0F" 0402 47.738,39.439 r270 top value=10.0
R30 "RK73H1ETTP10R0F" 0402 63.352,46.235 r270 top value=10.0
R31 "CRCW0402249RFKED" 0402 50.347,40.133 r0 top value=249
R32 "CRCW0402249RFKED" 0402 67.821,46.425 r270 top value=249
R33 "ERJ-2RKF1002X" 0402 39.96,94.385 r270 top value=10.0k
R34 "RC0402JR-070RL" 0402 53.917,94.416 r270 top value=0
R35 "RC0402JR-070RL" 0402 57.627,94.416 r270 top value=0
R36 "RC0402JR-070RL" 0402 58.863,94.416 r270 top value=0
R37 "RC0402JR-070RL" 0402 58.955,103.903 r90 top value=0
R38 "RC0402JR-070RL" 0402 57.865,103.903 r90 top value=0
R39 "ERJ-2RKF4701X" 0402 53.316,96.456 r180 top value=4.70k
R40 "RK73H1ETTP10R0F" 0402 35.3,21.396 r90 bottom value=10.0
R41 "RK73H1ETTP10R0F" 0402 49.196,22.428 r90 bottom value=10.0
R42 "RMCF0402JT100R" 0402 52.504,104.055 r90 top value=100
R43 "RMCF0402JT100R" 0402 52.504,101.2 r270 top value=100
R44 "RK73H1ETTP10R0F" 0402 37.432,21.935 r180 bottom value=10.0
R45 "RK73H1ETTP10R0F" 0402 37.432,26.751 r180 bottom value=10.0
R46 "RC0402FR-0715KL" 0402 37.406,116.641 r270 top value=15.0k
R47 "RC0402FR-0715KL" 0402 36.146,116.641 r90 top value=15.0k
R48 "RC0402FR-07470KL" 0402 34.856,116.623 r90 top value=470k
R49 "MCR01MZPF10R0" 0402 33.546,116.623 r90 top value=10.0
R50 "ERJ-2RKF1001X" 0402 37.569,116.732 r0 bottom value=1.00k
R51 "MCR01MZPF10R0" 0402 42.327,118.426 r90 bottom value=10.0
R52 "ERJ-2RKF1001X" 0402 43.207,125.244 r0 bottom value=1.00k
R53 "ERJ-2RKF1001X" 0402 37.569,117.958 r0 bottom value=1.00k
R54 "MCR01MZPF10R0" 0402 41.087,118.426 r90 bottom value=10.0
R55 "DNP" 0402 38.837,125.958 r90 bottom value=0
R56 "RMCF0402JT100R" 0402 32.985,119.996 r0 top value=100
R57 "RC0402FR-0715KL" 0402 36.553,119.996 r180 top value=15.0k
R58 "ERJ-2RKF1002X" 0402 40.978,128.105 r90 top value=10.0k
R59 "RC0402FR-0715KL" 0402 36.533,118.641 r0 top value=15.0k
R60 "ERJ-2RKF1002X" 0402 32.985,118.641 r180 top value=10.0k
R61 "RMCF0402JT100R" 0402 36.472,104.052 r90 top value=100
R62 "RK73H1ETTP10R0F" 0402 39.34,28.399 r180 top value=10.0
R63 "RK73H1ETTP10R0F" 0402 50.851,22.784 r270 top value=10.0
R64 "RMCF0402JT100R" 0402 36.472,101.2 r270 top value=100
R65 "RK73H1ETTP10R0F" 0402 39.34,25.773 r180 top value=10.0
R66 "RK73H1ETTP10R0F" 0402 39.34,20.457 r180 top value=10.0
R67 "CRCW04021R00FKED" 0402 36.007,137.144 r90 top value=1.00
R68 "ERJ-2RKF1002X" 0402 33.988,122.732 r90 bottom value=10.0k
R70 "CRCW04021R00FKED" 0402 35.298,134.757 r180 top value=1.00
R71 "RK73H1ETTP10R0F" 0402 43.807,137.957 r90 bottom value=10.0
R72 "ERJ-2RKF2201X" 0402 42.431,137.912 r270 bottom value=2.20k
R73 "CRCW040233K2FKED" 0402 46.72,135.222 r270 bottom value=33.2k
R74 "CRCW040233K2FKED" 0402 43.075,126.028 r0 top value=33.2k
R75 "CRCW040233K2FKED" 0402 45.317,135.222 r90 bottom value=33.2k
R76 "RT0402BRD0720KL" 0402 40.01,126.028 r0 top value=20.0k
R77 "ERJ-2RKF1501X" 0402 43.807,135.203 r90 bottom value=1.50k
R78 "ERJ-2RKF1501X" 0402 37.138,126.628 r270 top value=1.50k
R79 "ERJ-2RKF1002X" 0402 43.072,140.261 r0 bottom value=10.0k
R80 "ERJ-2RKF1203X" 0402 43.207,126.565 r0 bottom value=120k
R81 "CRCW040222K0JNED" 0402 40.95,141.616 r270 bottom value=22k
R82 "CRCW040222K0JNED" 0402 34.924,143.829 r180 bottom value=22k
R83 "RC0402FR-07100RL" 0402 44.136,137.854 r0 top value=100
R84 "CRCW040222K0JNED" 0402 36.894,143.229 r90 bottom value=22k
R85 "RC0402JR-070RL" 0402 34.906,108.628 r270 top value=0
R86 "CRCW040222K0JNED" 0402 33.585,108.628 r90 top value=22k
R87 "CRCW040222K0JNED" 0402 33.585,111.286 r90 top value=22k
R88 "CRCW040222K0JNED" 0402 33.585,113.931 r270 top value=22k
R90 "ERJ-2RKF1001X" 0402 46.478,132.321 r90 bottom value=1.00k
R91 "RT0402BRD0720KL" 0402 35.63,122.06 r270 top value=20.0k
R92 "ERJ-2RKF1001X" 0402 34.007,137.918 r180 top value=1.00k
R94 "ERJ-2RKF1501X" 0402 44.363,133.88 r270 top value=1.50k
R95 "ERJ-2RKF2201X" 0402 37.63,125.958 r270 bottom value=2.20k
R97 "CRCW040222K0JNED" 0402 42.201,137.144 r90 top value=22k
R98 "RC0402JR-0751RL" 0402 34.007,136.434 r0 top value=51
R99 "NCU15WF104E6SRC" FP-NCU15WF104E6SRC_0402-MFG 50.764,96.904 r0 top value=100k
R100 "RC0402JR-070RL" 0402 39.04,139.531 r180 top value=0
R101 "RG1005P-202-B-T5" 0402 39.04,141.66 r90 top value=2.00k
R103 "ERJ2RKF3902X" 0402 34.399,140.519 r270 bottom value=39.0k
R104 "RC0402FR-07100KL" 0402 36.894,137.874 r270 bottom value=100k
R106 "CRCW04025R62FKED" 0402 32.995,140.528 r90 bottom value=5.62
R108 "CRCW040222K0JNED" 0402 32.995,143.176 r90 bottom value=22k
R109 "DNP" 0402 37.432,25.547 r180 bottom value=10.0
R110 "DNP" 0402 39.34,21.786 r180 top value=10.0
R111 "ERJ-2RKF1002X" 0402 55.153,94.416 r270 top value=10.0k
R112 "CRCW0603100KJNEAC" 0603 12.473,32.274 r180 top value=100k
R113 "RT0603BRD07120KL" 0603 12.473,33.841 r0 top value=120k
R114 "RC0603FR-0733KL" 0603 23.518,28.353 r90 top value=33.0k
R115 "CRT0603-BY-10R0ELF" 0603 28.607,35.316 r270 top value=10.0
R116 "RC0603FR-0733KL" 0603 20.688,27.454 r0 top value=33.0k
R117 "RT0603DRE0712KL" 0603 11.661,29.659 r90 top value=12.0k
R118 "RC0603FR-0743KL" 0603 26.098,34.457 r0 top value=43.0k
R119 "RC0603FR-0722KL" 0603 26.098,36.143 r0 top value=22.0k
R120 "CRCW0603100KJNEAC" 0603 16.795,29.211 r180 top value=100k
R121 "RC0603FR-079K1L" 0603 26.098,31.087 r180 top value=9.10k
R122 "RT0603BRD074K7L" 0603 26.098,32.773 r180 top value=4.70k
R123 "RT0603BRD07470RL" 0603 21.612,55.97 r90 top value=470
R124 "RC0603FR-07110KL" 0603 25.128,61.071 r0 top value=110k
R125 "RC0603FR-07110KL" 0603 28.435,61.052 r0 top value=110k
R126 "RT0603BRD071K02L" 0603 27.632,65.181 r90 top value=1.02k
R127 "RG1608P-682-B-T5" 0603 29.248,65.181 r270 top value=6.80k
R128 "RT0603BRD074K7L" 0603 28.435,62.67 r0 top value=4.70k
R129 "CRCW04025R62FKED" 0402 26.511,102.189 r0 top value=5.62
R130 "CRCW08050000Z0EAHP" 0805_HV 26.466,69.286 r90 bottom value=0
R131 "RT0805BRD079K65L" 0805_HV 15.661,68.509 r0 bottom value=9.65k
R132 "RCS04022R20FKED" 0402 27.122,112.721 r270 top value=2.20
R134 "ERJ-2RKF1002X" 0402 56.39,94.416 r270 top value=10.0k
R135 "CRCW04023K30JNED" 0402 32.191,127.228 r90 top value=3.3k
R136 "CRCW04023K30JNED" 0402 33.74,127.228 r90 top value=3.3k
Rlimit1 "RT0805BRD0718K2L" 0805_HV 15.661,73.056 r0 bottom value=18.2k
RS1 "RC1206JR-070RL" 1206 45.666,124.087 r90 bottom value=0
RSENSE1 "WSLF25121L000FEB" FP-WSLF25121L000FEB_2512-MFG 47.288,118.712 r0 bottom
T1 "P-24015" FP-P-24015_SMT_XFRMR_29MM0_31MM1-MFG 49.833,72.747 r0 top
T2 "750316769" Wurth_750316769 21.621,78.992 r90 bottom value=350uH
T3 "CB35-36-CY" CB35-36-CY 31.61,-7.41 r90 top
T4 "CB35-36-CY" CB35-36-CY 32.341,174.205 r270 top
T5 "CB35-36-CY" CB35-36-CY 57.114,-7.41 r90 top
T6 "CB35-36-CY" CB35-36-CY 57.369,174.205 r270 top
U1 "LMG2100R026" VBN0016A-MFG 44.033,99.517 r90 top
U2 "LMG3100R017" VBE0015A-MFG 38.086,45.125 r180 top
U3 "LMG3100R017" VBE0015A-MFG 55.591,52.106 r180 top
U4 "LMG2100R026" VBN0016A-MFG 60.424,99.542 r90 top
U5 "LMG3100R017" VBE0015A-MFG 46.118,45.125 r180 top
U6 "LMG3100R017" VBE0015A-MFG 64.037,52.106 r180 top
U7 "ISO6720BDR" D0008A-MFG 43.055,23.729 r0 bottom
U8 "TLV365DBVR" DBV0005A-MFG 34.551,117.183 r270 bottom
U9 "ISO6720BDR" D0008A-MFG 45.07,23.708 r0 top
U10 "UCD3138064RMHR" FP-RMH0040A-MFG 37.511,131.57 r90 bottom
U11 "TLV76150DCYR" DCY0004A-MFG 17.432,87.02 r90 top
U12 "TLV76133DCYR" DCY0004A-MFG 24.619,87.07 r90 top
U13 "LM5169FQDDAR" DDA0008E-MFG 18.839,33.01 r0 top
U14 "TLV76150DCYR" DCY0004A-MFG 27.635,46.986 r90 top
U15 "UCC5350SBDR" D0008A-MFG 26.522,106.755 r270 top
U16 "SN6507DGQ" DGQ0010D-MFG 21.563,68.795 r180 bottom

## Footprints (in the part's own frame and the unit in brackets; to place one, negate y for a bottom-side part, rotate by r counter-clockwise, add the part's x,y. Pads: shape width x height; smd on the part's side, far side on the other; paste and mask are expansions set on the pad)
0402 [mm] "0402 from SM-752 data"
  rect 0.8x0.6 smd: 1(-0.6,0) 2(0.6,0)
  silkscreen extent -1.22,-0.52 1.22,0.52, body extent -0.55,-0.3 0.55,0.3, height 0.6
0402M [mm] "0402 from SM-752 data"
  rect 1x0.7 smd: 1(-0.7,0) 2(0.7,0)
  silkscreen extent -1.5,-0.64 1.51,0.65, body extent -0.55,-0.3 0.55,0.3, height 0.6
0603 [mm] "0603 from SM-752 data"
  rect 1x0.95 smd: 1(-0.8,0) 2(0.8,0)
  silkscreen extent -1.52,-0.69 1.52,0.69, body extent -0.87,-0.47 0.87,0.47, height 1
0805_HV [mil] "0805 with 30mil clearance between pads"
  rect 50x63 smd: 1(-40,0) 2(40,0)
  silkscreen extent -74,-40 74,40, body extent -43,-29 43,29, height 57
1206 [mm] "1206 from SM-752 data"
  rect 1.3x1.85 smd: 1(-1.45,0) 2(1.45,0)
  silkscreen extent -2.4,-1.21 2.4,1.21, body extent -1.7,-0.9 1.7,0.9, height 1.35
1210 [mm] "1210 from SM-752 data"
  rect 1.3x2.7 smd: 1(-1.45,0) 2(1.45,0)
  silkscreen extent -2.32,-1.57 2.32,1.57, body extent -1.7,-1.35 1.7,1.35, height 1.35
2512 [mm] "Chip Resistor, Body 6.3x3.2mm, IPC Medium Density"
  rect 1.3x3.4 smd: 1(-2.95,0) 2(2.95,0)
  silkscreen extent -1.9,-1.6 1.9,1.6, body extent -3.22,-1.67 3.22,1.67, height 0.71
CB35-36-CY [mil] "Terminal 50A Lug"
  rect 550x380 hole 188 copper offset -45,0 paste-190: 1(0,0)
  body extent -960,-189 230,191, height 614
CE_Mark_5mm [mm] "Minimum text height for CE Mark"
  silkscreen extent -3.5,-2.5 3.5,2.5
D0008A-MFG [mm]
  rrect17% 1.55x0.6 smd paste+0 mask+0: 1(-2.7,1.905) 2(-2.7,0.635) 3(-2.7,-0.635) 4(-2.7,-1.905) 5(2.7,-1.905) 6(2.7,-0.635) 7(2.7,0.635) 8(2.7,1.905)
  silkscreen extent -4.17,-2.5 1.5,2.5, body extent -3,-2.45 3,2.45, height 1.75
DBV0005A-MFG [mm]
  rrect17% 1.1x0.6 smd paste+0 mask+0: 1(-1.3,0.95) 2(-1.3,0) 3(-1.3,-0.95) 4(1.3,-0.95) 5(1.3,0.95)
  silkscreen extent -2.52,-1.53 0.87,1.53, body extent -1.4,-1.45 1.4,1.45, height 1.45
DCY0004A-MFG [mm]
  rrect11% 2.15x0.95 smd paste+0 mask+0: 1(-2.9,2.3) 2(-2.9,0) 3(-2.9,-2.3)
  rrect5% 2.15x3.25 smd paste+0 mask+0: 4(2.9,0)
  silkscreen extent -4.65,-3.35 1.85,3.35, body extent -4.08,-3.45 4.08,3.45, height 0.25
DDA0008E-MFG [mm]
  rrect20% 2.2x0.5 smd paste-1000 mask+0: 1(-2.875,1.905) 2(-2.875,0.635) 3(-2.875,-0.635) 4(-2.875,-1.905) 5(2.875,-1.905) 6(2.875,-0.635) 7(2.875,0.635) 8(2.875,1.905)
  rrect3% 2.95x4.9 smd paste-1000 mask-1000: 9(0,0)
  silkscreen extent -4.67,-2.83 2,2.83, body extent -4.08,-2.68 4.08,2.68, height 0.25
DGQ0010D-MFG [mm]
  rrect33% 1.45x0.3 smd paste+0 mask+0: 1(-2.2,1) 2(-2.2,0.5) 3(-2.2,0) 4(-2.2,-0.5) 5(-2.2,-1) 6(2.2,-1) 7(2.2,-0.5) 8(2.2,0) 9(2.2,0.5) 10(2.2,1)
  rrect5% 2.2x3.1 smd paste-1000 mask-1000: 11(0,0)
  silkscreen extent -3.6,-1.92 1.55,1.92, body extent -2.46,-1.5 2.46,1.5, height 1.1
FCC_disclaimer [mm]
FP-1SMA70AT3G_SMA-MFG [mm]
  rrect5% 2x2 smd paste+0 mask+0: 1(-2,0) 2(2,0)
  silkscreen extent -3.67,-1.46 2.28,1.46, body extent -2.61,-1.3 2.61,1.3, height 2.2
FP-74439369010_SMD_11MM6_10MM5-MFG [mm] "Recommended Land Pattern"
  rrect4% 9x2.5 smd paste+0 mask+0: 1(0,3.2) 2(0,-3.2)
  silkscreen extent -5.95,-5.4 5.95,6.03, body extent -6.05,-5.5 6.05,5.5, height 0.25
FP-885012206120_0603-MFG [mm]
  rrect13% 0.8x0.8 smd paste+0 mask+0: 1(-0.75,0) 2(0.75,0)
  silkscreen extent -0.85,-0.77 0.85,0.77, body extent -1.25,-0.55 1.25,0.55, height 0.25
FP-BSC074N15NS5ATMA1_PG-TSON-8-3-MFG [mm]
  rrect10% 3.08x1 smd paste-1000 mask-1000: 1-2-3(-0.635,-2.75)
  rrect19% 0.54x1 smd paste-1000 mask+0: 4(1.905,-2.75)
  rrect2% 4.45x4.4 smd paste-1000 mask-1000: 5-6-7-8(0,1.05)
  silkscreen extent -2.5,-4.03 2.5,-1.53, body extent -2.5,-3 2.5,3, height 1.1
FP-C3216X6S2A106K160AC_1206-MFG [mm]
  rrect9% 1.1x1.35 smd paste+0 mask+0: 1(-1.65,0) 2(1.65,0)
  silkscreen extent -0.72,-0.95 0.72,0.95, body extent -1.6,-0.8 1.6,0.8, height 1.9
FP-EMX1DXV6T5_SOT563-MFG [mm]
  rrect33% 0.45x0.3 smd paste+0 mask+0: 1(-0.675,0.5) 2(-0.675,0) 3(-0.675,-0.5) 4(0.675,-0.5) 5(0.675,0) 6(0.675,0.5)
  silkscreen extent -1.6,-0.8 0,0.8, body extent -0.8,-0.8 0.8,0.8, height 0.6
FP-MSD1260H-154KED_SMT_CMC_12MM3_12MM3-MFG [mm]
  rrect5% 4x2 smd paste+0 mask+0: 1(-4.25,1.75) 2(-4.25,-1.75) 3(4.25,-1.75) 4(4.25,1.75)
  silkscreen extent -6.92,-6.15 6.15,6.15, body extent -6.35,-6.25 6.35,6.25, height 0.25
FP-NCU15WF104E6SRC_0402-MFG [mm]
  rrect22% 0.45x0.5 smd paste+0 mask+0: 1(-0.425,0) 2(0.425,0)
  silkscreen extent -0.53,-0.63 0.53,0.63, body extent -0.5,-0.25 0.5,0.25, height 0.55
FP-P-24015_SMT_XFRMR_29MM0_31MM1-MFG [mm] "Recommended Land Pattern"
  rrect3% 11.65x3.5 smd paste+0 mask+0: 1(-7.325,-13.25) 2(7.325,-13.25)
  rrect3% 11.15x3.5 smd paste+0 mask+0: 3(7.575,13.25) 4(-7.575,13.25)
  Keep-Out Layer board cut-out: -15.65,10.55 15.65,10.55 15.65,-10.55 -15.65,-10.55
  silkscreen extent -15.55,-14.6 15.55,14.6, body extent -15.65,-15.1 15.65,15.1, height 0.25
FP-PNE20020ERX_SOD123W-MFG [mm]
  rrect8% 1.2x1.2 smd paste-1000 mask+0: 1(-1.4,0) 2(1.4,0)
  silkscreen extent -2.67,-0.95 0.43,0.95, body extent -1.75,-0.85 1.75,0.85, height 1.1
FP-RMH0040A-MFG [mm]
  round 0.216 smd paste+0 mask+0: 1(-2.9,2.25) 2(-2.9,1.75) 3(-2.9,1.25) 4(-2.9,0.75) 5(-2.9,0.25) 6(-3.08,-0.25) 7(-3.08,-0.75) 8(-3.08,-1.25) 9(-3.08,-1.75) 10(-2.9,-2.25) 11(-2.25,-2.9) 12(-1.75,-2.9) 13(-1.25,-2.9) 14(-0.75,-2.9) 15(-0.25,-2.9) 16(0.25,-3.08) 17(0.75,-3.08) 18(1.25,-3.08) 19(1.75,-3.08) 20(2.25,-2.9) 21(2.9,-2.25) 22(2.9,-1.75) 23(2.9,-1.25) 24(2.9,-0.75) 25(2.9,-0.25) 26(2.912,0.25) 27(2.912,0.75) 28(2.912,1.25) 29(2.912,1.75) 30(2.9,2.25) 31(2.25,2.9) 32(1.75,2.9) 33(1.25,2.9) 34(0.75,2.9) 35(0.25,2.9) 36(-0.25,2.912) 37(-0.75,2.912) 38(-1.25,2.912) 39(-1.75,2.912) 40(-2.25,2.9)
  rect 0.28x0.28 smd paste+0 mask+0: 41(-2.76,2.76) 42(2.76,2.76) 43(-2.76,-2.76) 44(2.76,-2.76)
  rect 4.15x4.15 smd paste-1000 mask+0: 45(0,0)
  Top Layer region: -3.2,0.87 -2.72,0.87 -2.674,0.861 -2.635,0.835 -2.609,0.796 -2.6,0.75 -2.6,0.75 -2.609,0.704 -2.635,0.665 -2.674,0.639 -2.72,0.63 -2.72,0.63 -3.2,0.63
  Top Layer region: -3.2,2.37 -2.72,2.37 -2.674,2.361 -2.635,2.335 -2.609,2.296 -2.6,2.25 -2.6,2.25 -2.609,2.204 -2.635,2.165 -2.674,2.139 -2.72,2.13 -2.72,2.13 -3.2,2.13
  Top Layer region: -3.2,-0.13 -2.72,-0.13 -2.674,-0.139 -2.635,-0.165 -2.609,-0.204 -2.6,-0.25 -2.6,-0.25 -2.609,-0.296 -2.635,-0.335 -2.674,-0.361 -2.72,-0.37 -2.72,-0.37 -3.2,-0.37
  Top Layer region: 3.2,0.13 2.72,0.13 2.674,0.139 2.635,0.165 2.609,0.204 2.6,0.25 2.6,0.25 2.609,0.296 2.635,0.335 2.674,0.361 2.72,0.37 2.72,0.37 3.2,0.37
  Top Layer region: 3.2,1.63 2.72,1.63 2.674,1.639 2.635,1.665 2.609,1.704 2.6,1.75 2.6,1.75 2.609,1.796 2.635,1.835 2.674,1.861 2.72,1.87 2.72,1.87 3.2,1.87
  Top Layer region: 3.2,2.13 2.72,2.13 2.674,2.139 2.635,2.165 2.609,2.204 2.6,2.25 2.6,2.25 2.609,2.296 2.635,2.335 2.674,2.361 2.72,2.37 2.72,2.37 3.2,2.37
  Top Layer region: 1.87,3.2 1.87,2.72 1.861,2.674 1.835,2.635 1.796,2.609 1.75,2.6 1.75,2.6 1.704,2.609 1.665,2.635 1.639,2.674 1.63,2.72 1.63,2.72 1.63,3.2
  Top Layer region: 0.87,3.2 0.87,2.72 0.861,2.674 0.835,2.635 0.796,2.609 0.75,2.6 0.75,2.6 0.704,2.609 0.665,2.635 0.639,2.674 0.63,2.72 0.63,2.72 0.63,3.2
  Top Layer region: -0.13,3.2 -0.13,2.72 -0.139,2.674 -0.165,2.635 -0.204,2.609 -0.25,2.6 -0.25,2.6 -0.296,2.609 -0.335,2.635 -0.361,2.674 -0.37,2.72 -0.37,2.72 -0.37,3.2
  Top Layer region: -3.2,1.87 -2.72,1.87 -2.674,1.861 -2.635,1.835 -2.609,1.796 -2.6,1.75 -2.6,1.75 -2.609,1.704 -2.635,1.665 -2.674,1.639 -2.72,1.63 -2.72,1.63 -3.2,1.63
  Top Layer region: -3.2,1.37 -2.72,1.37 -2.674,1.361 -2.635,1.335 -2.609,1.296 -2.6,1.25 -2.6,1.25 -2.609,1.204 -2.635,1.165 -2.674,1.139 -2.72,1.13 -2.72,1.13 -3.2,1.13
  Top Layer region: -3.2,0.37 -2.72,0.37 -2.674,0.361 -2.635,0.335 -2.609,0.296 -2.6,0.25 -2.6,0.25 -2.609,0.204 -2.635,0.165 -2.674,0.139 -2.72,0.13 -2.72,0.13 -3.2,0.13
  Top Layer region: -3.2,-0.63 -2.72,-0.63 -2.674,-0.639 -2.635,-0.665 -2.609,-0.704 -2.6,-0.75 -2.6,-0.75 -2.609,-0.796 -2.635,-0.835 -2.674,-0.861 -2.72,-0.87 -2.72,-0.87 -3.2,-0.87
  Top Layer region: -3.2,-1.13 -2.72,-1.13 -2.674,-1.139 -2.635,-1.165 -2.609,-1.204 -2.6,-1.25 -2.6,-1.25 -2.609,-1.296 -2.635,-1.335 -2.674,-1.361 -2.72,-1.37 -2.72,-1.37 -3.2,-1.37
  Top Layer region: -3.2,-1.63 -2.72,-1.63 -2.674,-1.639 -2.635,-1.665 -2.609,-1.704 -2.6,-1.75 -2.6,-1.75 -2.609,-1.796 -2.635,-1.835 -2.674,-1.861 -2.72,-1.87 -2.72,-1.87 -3.2,-1.87
  Top Layer region: -3.2,-2.13 -2.72,-2.13 -2.674,-2.139 -2.635,-2.165 -2.609,-2.204 -2.6,-2.25 -2.6,-2.25 -2.609,-2.296 -2.635,-2.335 -2.674,-2.361 -2.72,-2.37 -2.72,-2.37 -3.2,-2.37
  Top Layer region: -2.37,-3.2 -2.37,-2.72 -2.361,-2.674 -2.335,-2.635 -2.296,-2.609 -2.25,-2.6 -2.25,-2.6 -2.204,-2.609 -2.165,-2.635 -2.139,-2.674 -2.13,-2.72 -2.13,-2.72 -2.13,-3.2
  Top Layer region: -1.87,-3.2 -1.87,-2.72 -1.861,-2.674 -1.835,-2.635 -1.796,-2.609 -1.75,-2.6 -1.75,-2.6 -1.704,-2.609 -1.665,-2.635 -1.639,-2.674 -1.63,-2.72 -1.63,-2.72 -1.63,-3.2
  Top Layer region: -1.37,-3.2 -1.37,-2.72 -1.361,-2.674 -1.335,-2.635 -1.296,-2.609 -1.25,-2.6 -1.25,-2.6 -1.204,-2.609 -1.165,-2.635 -1.139,-2.674 -1.13,-2.72 -1.13,-2.72 -1.13,-3.2
  Top Layer region: -0.87,-3.2 -0.87,-2.72 -0.861,-2.674 -0.835,-2.635 -0.796,-2.609 -0.75,-2.6 -0.75,-2.6 -0.704,-2.609 -0.665,-2.635 -0.639,-2.674 -0.63,-2.72 -0.63,-2.72 -0.63,-3.2
  Top Layer region: -0.37,-3.2 -0.37,-2.72 -0.361,-2.674 -0.335,-2.635 -0.296,-2.609 -0.25,-2.6 -0.25,-2.6 -0.204,-2.609 -0.165,-2.635 -0.139,-2.674 -0.13,-2.72 -0.13,-2.72 -0.13,-3.2
  Top Layer region: 0.13,-3.2 0.13,-2.72 0.139,-2.674 0.165,-2.635 0.204,-2.609 0.25,-2.6 0.25,-2.6 0.296,-2.609 0.335,-2.635 0.361,-2.674 0.37,-2.72 0.37,-2.72 0.37,-3.2
  Top Layer region: 0.63,-3.2 0.63,-2.72 0.639,-2.674 0.665,-2.635 0.704,-2.609 0.75,-2.6 0.75,-2.6 0.796,-2.609 0.835,-2.635 0.861,-2.674 0.87,-2.72 0.87,-2.72 0.87,-3.2
  Top Layer region: 1.13,-3.2 1.13,-2.72 1.139,-2.674 1.165,-2.635 1.204,-2.609 1.25,-2.6 1.25,-2.6 1.296,-2.609 1.335,-2.635 1.361,-2.674 1.37,-2.72 1.37,-2.72 1.37,-3.2
  Top Layer region: 1.63,-3.2 1.63,-2.72 1.639,-2.674 1.665,-2.635 1.704,-2.609 1.75,-2.6 1.75,-2.6 1.796,-2.609 1.835,-2.635 1.861,-2.674 1.87,-2.72 1.87,-2.72 1.87,-3.2
  Top Layer region: 2.13,-3.2 2.13,-2.72 2.139,-2.674 2.165,-2.635 2.204,-2.609 2.25,-2.6 2.25,-2.6 2.296,-2.609 2.335,-2.635 2.361,-2.674 2.37,-2.72 2.37,-2.72 2.37,-3.2
  Top Layer region: 3.2,-2.37 2.72,-2.37 2.674,-2.361 2.635,-2.335 2.609,-2.296 2.6,-2.25 2.6,-2.25 2.609,-2.204 2.635,-2.165 2.674,-2.139 2.72,-2.13 2.72,-2.13 3.2,-2.13
  Top Layer region: 3.2,-1.87 2.72,-1.87 2.674,-1.861 2.635,-1.835 2.609,-1.796 2.6,-1.75 2.6,-1.75 2.609,-1.704 2.635,-1.665 2.674,-1.639 2.72,-1.63 2.72,-1.63 3.2,-1.63
  Top Layer region: 3.2,-1.37 2.72,-1.37 2.674,-1.361 2.635,-1.335 2.609,-1.296 2.6,-1.25 2.6,-1.25 2.609,-1.204 2.635,-1.165 2.674,-1.139 2.72,-1.13 2.72,-1.13 3.2,-1.13
  Top Layer region: 3.2,-0.87 2.72,-0.87 2.674,-0.861 2.635,-0.835 2.609,-0.796 2.6,-0.75 2.6,-0.75 2.609,-0.704 2.635,-0.665 2.674,-0.639 2.72,-0.63 2.72,-0.63 3.2,-0.63
  Top Layer region: 3.2,-0.37 2.72,-0.37 2.674,-0.361 2.635,-0.335 2.609,-0.296 2.6,-0.25 2.6,-0.25 2.609,-0.204 2.635,-0.165 2.674,-0.139 2.72,-0.13 2.72,-0.13 3.2,-0.13
  Top Layer region: 3.2,0.63 2.72,0.63 2.674,0.639 2.635,0.665 2.609,0.704 2.6,0.75 2.6,0.75 2.609,0.796 2.635,0.835 2.674,0.861 2.72,0.87 2.72,0.87 3.2,0.87
  Top Layer region: 3.2,1.13 2.72,1.13 2.674,1.139 2.635,1.165 2.609,1.204 2.6,1.25 2.6,1.25 2.609,1.296 2.635,1.335 2.674,1.361 2.72,1.37 2.72,1.37 3.2,1.37
  Top Layer region: 2.37,3.2 2.37,2.72 2.361,2.674 2.335,2.635 2.296,2.609 2.25,2.6 2.25,2.6 2.204,2.609 2.165,2.635 2.139,2.674 2.13,2.72 2.13,2.72 2.13,3.2
  Top Layer region: 1.37,3.2 1.37,2.72 1.361,2.674 1.335,2.635 1.296,2.609 1.25,2.6 1.25,2.6 1.204,2.609 1.165,2.635 1.139,2.674 1.13,2.72 1.13,2.72 1.13,3.2
  Top Layer region: 0.37,3.2 0.37,2.72 0.361,2.674 0.335,2.635 0.296,2.609 0.25,2.6 0.25,2.6 0.204,2.609 0.165,2.635 0.139,2.674 0.13,2.72 0.13,2.72 0.13,3.2
  Top Layer region: -0.63,3.2 -0.63,2.72 -0.639,2.674 -0.665,2.635 -0.704,2.609 -0.75,2.6 -0.75,2.6 -0.796,2.609 -0.835,2.635 -0.861,2.674 -0.87,2.72 -0.87,2.72 -0.87,3.2
  Top Layer region: -1.13,3.2 -1.13,2.72 -1.139,2.674 -1.165,2.635 -1.204,2.609 -1.25,2.6 -1.25,2.6 -1.296,2.609 -1.335,2.635 -1.361,2.674 -1.37,2.72 -1.37,2.72 -1.37,3.2
  Top Layer region: -1.63,3.2 -1.63,2.72 -1.639,2.674 -1.665,2.635 -1.704,2.609 -1.75,2.6 -1.75,2.6 -1.796,2.609 -1.835,2.635 -1.861,2.674 -1.87,2.72 -1.87,2.72 -1.87,3.2
  Top Layer region: -2.13,3.2 -2.13,2.72 -2.139,2.674 -2.165,2.635 -2.204,2.609 -2.25,2.6 -2.25,2.6 -2.296,2.609 -2.335,2.635 -2.361,2.674 -2.37,2.72 -2.37,2.72 -2.37,3.2
  silkscreen extent -3.9,-3.45 3.45,3.45, body extent -3,-3 3,3, height 0.8
FP-SDM20U40-7_SOD523-MFG [mm]
  rrect17% 0.6x0.7 smd paste+0 mask+0: 1(-0.7,0) 2(0.7,0)
  silkscreen extent -1.7,-0.75 0.63,0.75, body extent -1.1,-0.53 1.1,0.53, height 0.25
FP-WSLF25121L000FEB_2512-MFG [mm]
  rrect6% 1.8x3.4 smd paste+0 mask+0: 1(-2.6,0) 2(2.6,0)
  silkscreen extent -1.33,-1.61 1.33,1.61, body extent -3.17,-1.51 3.17,1.51, height 0.81
Keystone_1902C [mil] "Hex Standoff, 4-40 threaded, nylon"
  round 1 on Mech4: 0(0,0)
  body extent -145,-126 146,126, height 501
M_1600x2500 [mm] "TH, 2-Leads, Dia 16mm, Pin Spacing 7.5mm"
  rect 1.6x1.6 hole 1.1: 1(-3.75,0)
  round 1.6 hole 1.1: 2(3.75,0)
  silkscreen extent -8.25,-8.25 8.25,8.25, body extent -8.19,-8.24 8.23,8.24, height 27.01
"NY PMS 440 0025 PH" [mm] "4-40 nylon screw and mounting hole"
  round 8 hole 3.2: 1(0,0)
  body extent -3.3,-3.3 3.3,3.3, height 2.69
SOT-23 [mm] "SOT23, 3-Leads, Body 2.9x1.3mm, Pitch 0.95mm, Lead Span 2.5mm, IPC Medium Density"
  rrect50% 1x0.6 smd: 1(-1.2,0.95) 2(-1.2,-0.95) 3(1.2,0)
  silkscreen extent -1.63,-1.5 0.7,1.5, body extent -1.16,-1.45 1.21,1.45, height 1
SOT-23L [mm] "SOT23, 3-Leads, Body 2.9x1.3mm, Pitch 0.95mm, Lead Span 2.5mm, IPC High Density"
  rrect50% 0.8x0.6 smd: 1(-1.1,0.95) 2(-1.1,-0.95) 3(1.1,0)
  silkscreen extent 0.1,-1.5 0.7,1.5, body extent -1.16,-1.45 1.21,1.45, height 1
TI_Stacked_Overlay_Small [mm]
  silkscreen extent -10.63,-2.49 10.63,2.49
